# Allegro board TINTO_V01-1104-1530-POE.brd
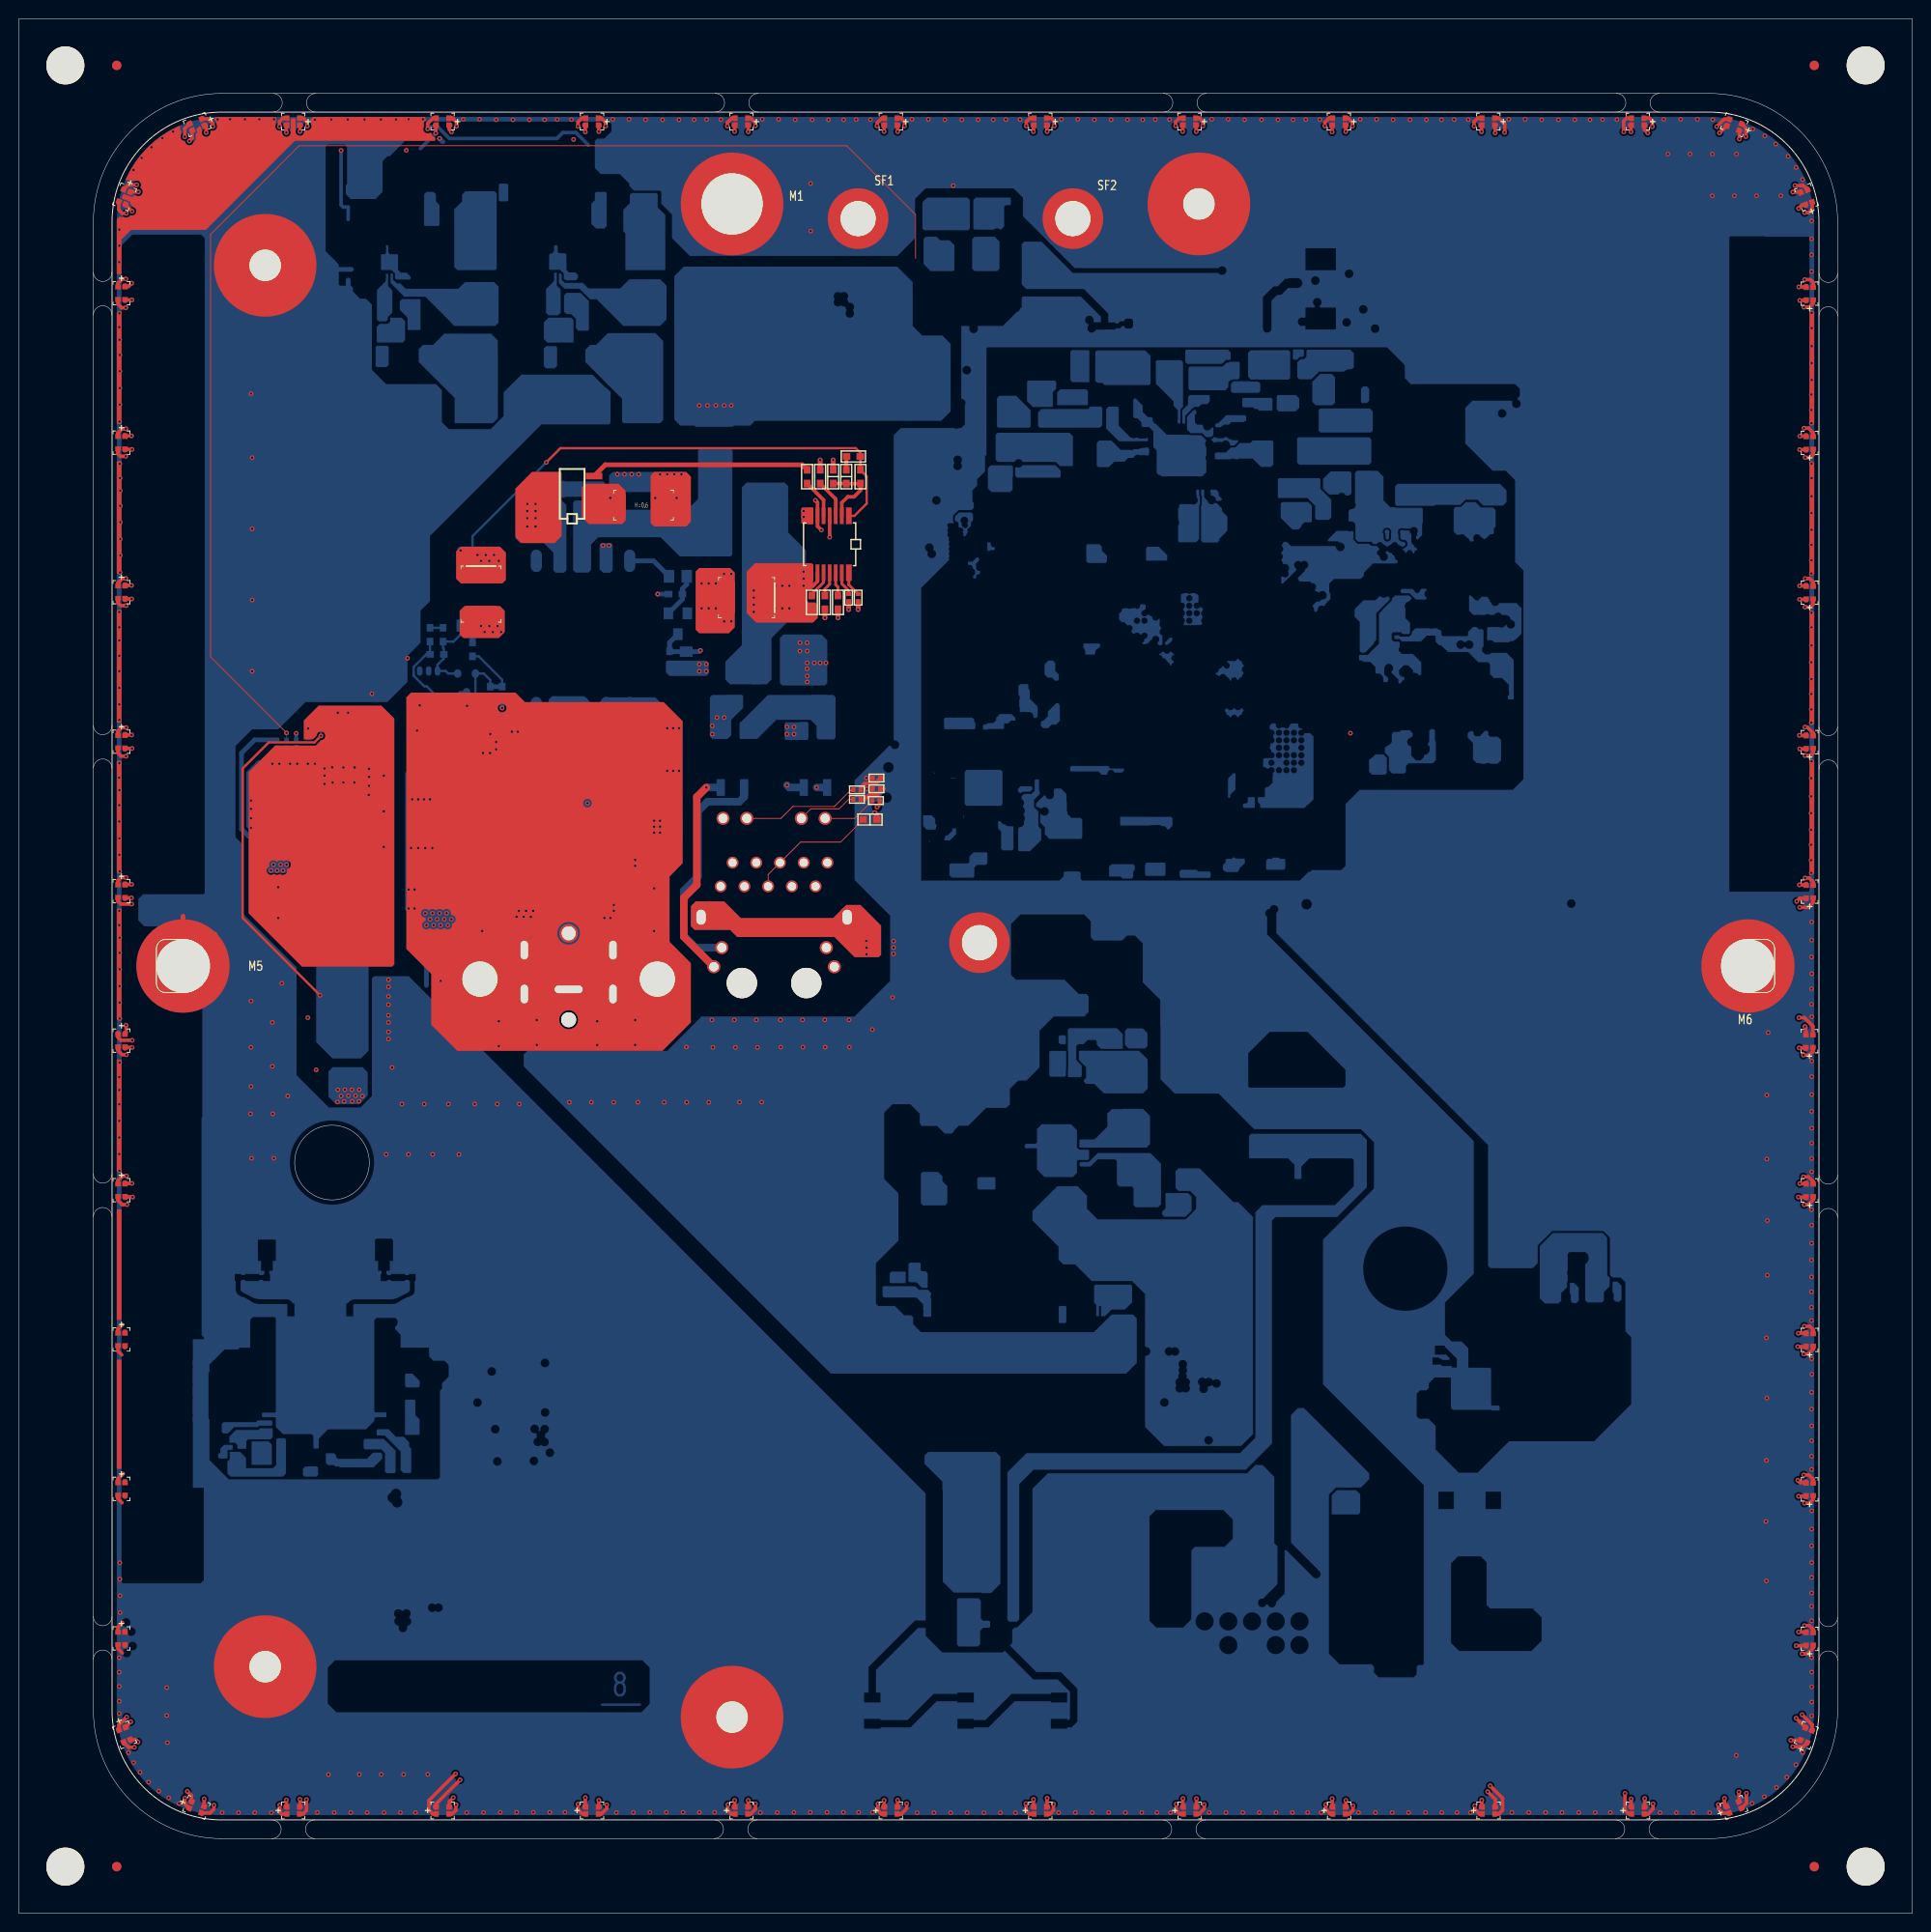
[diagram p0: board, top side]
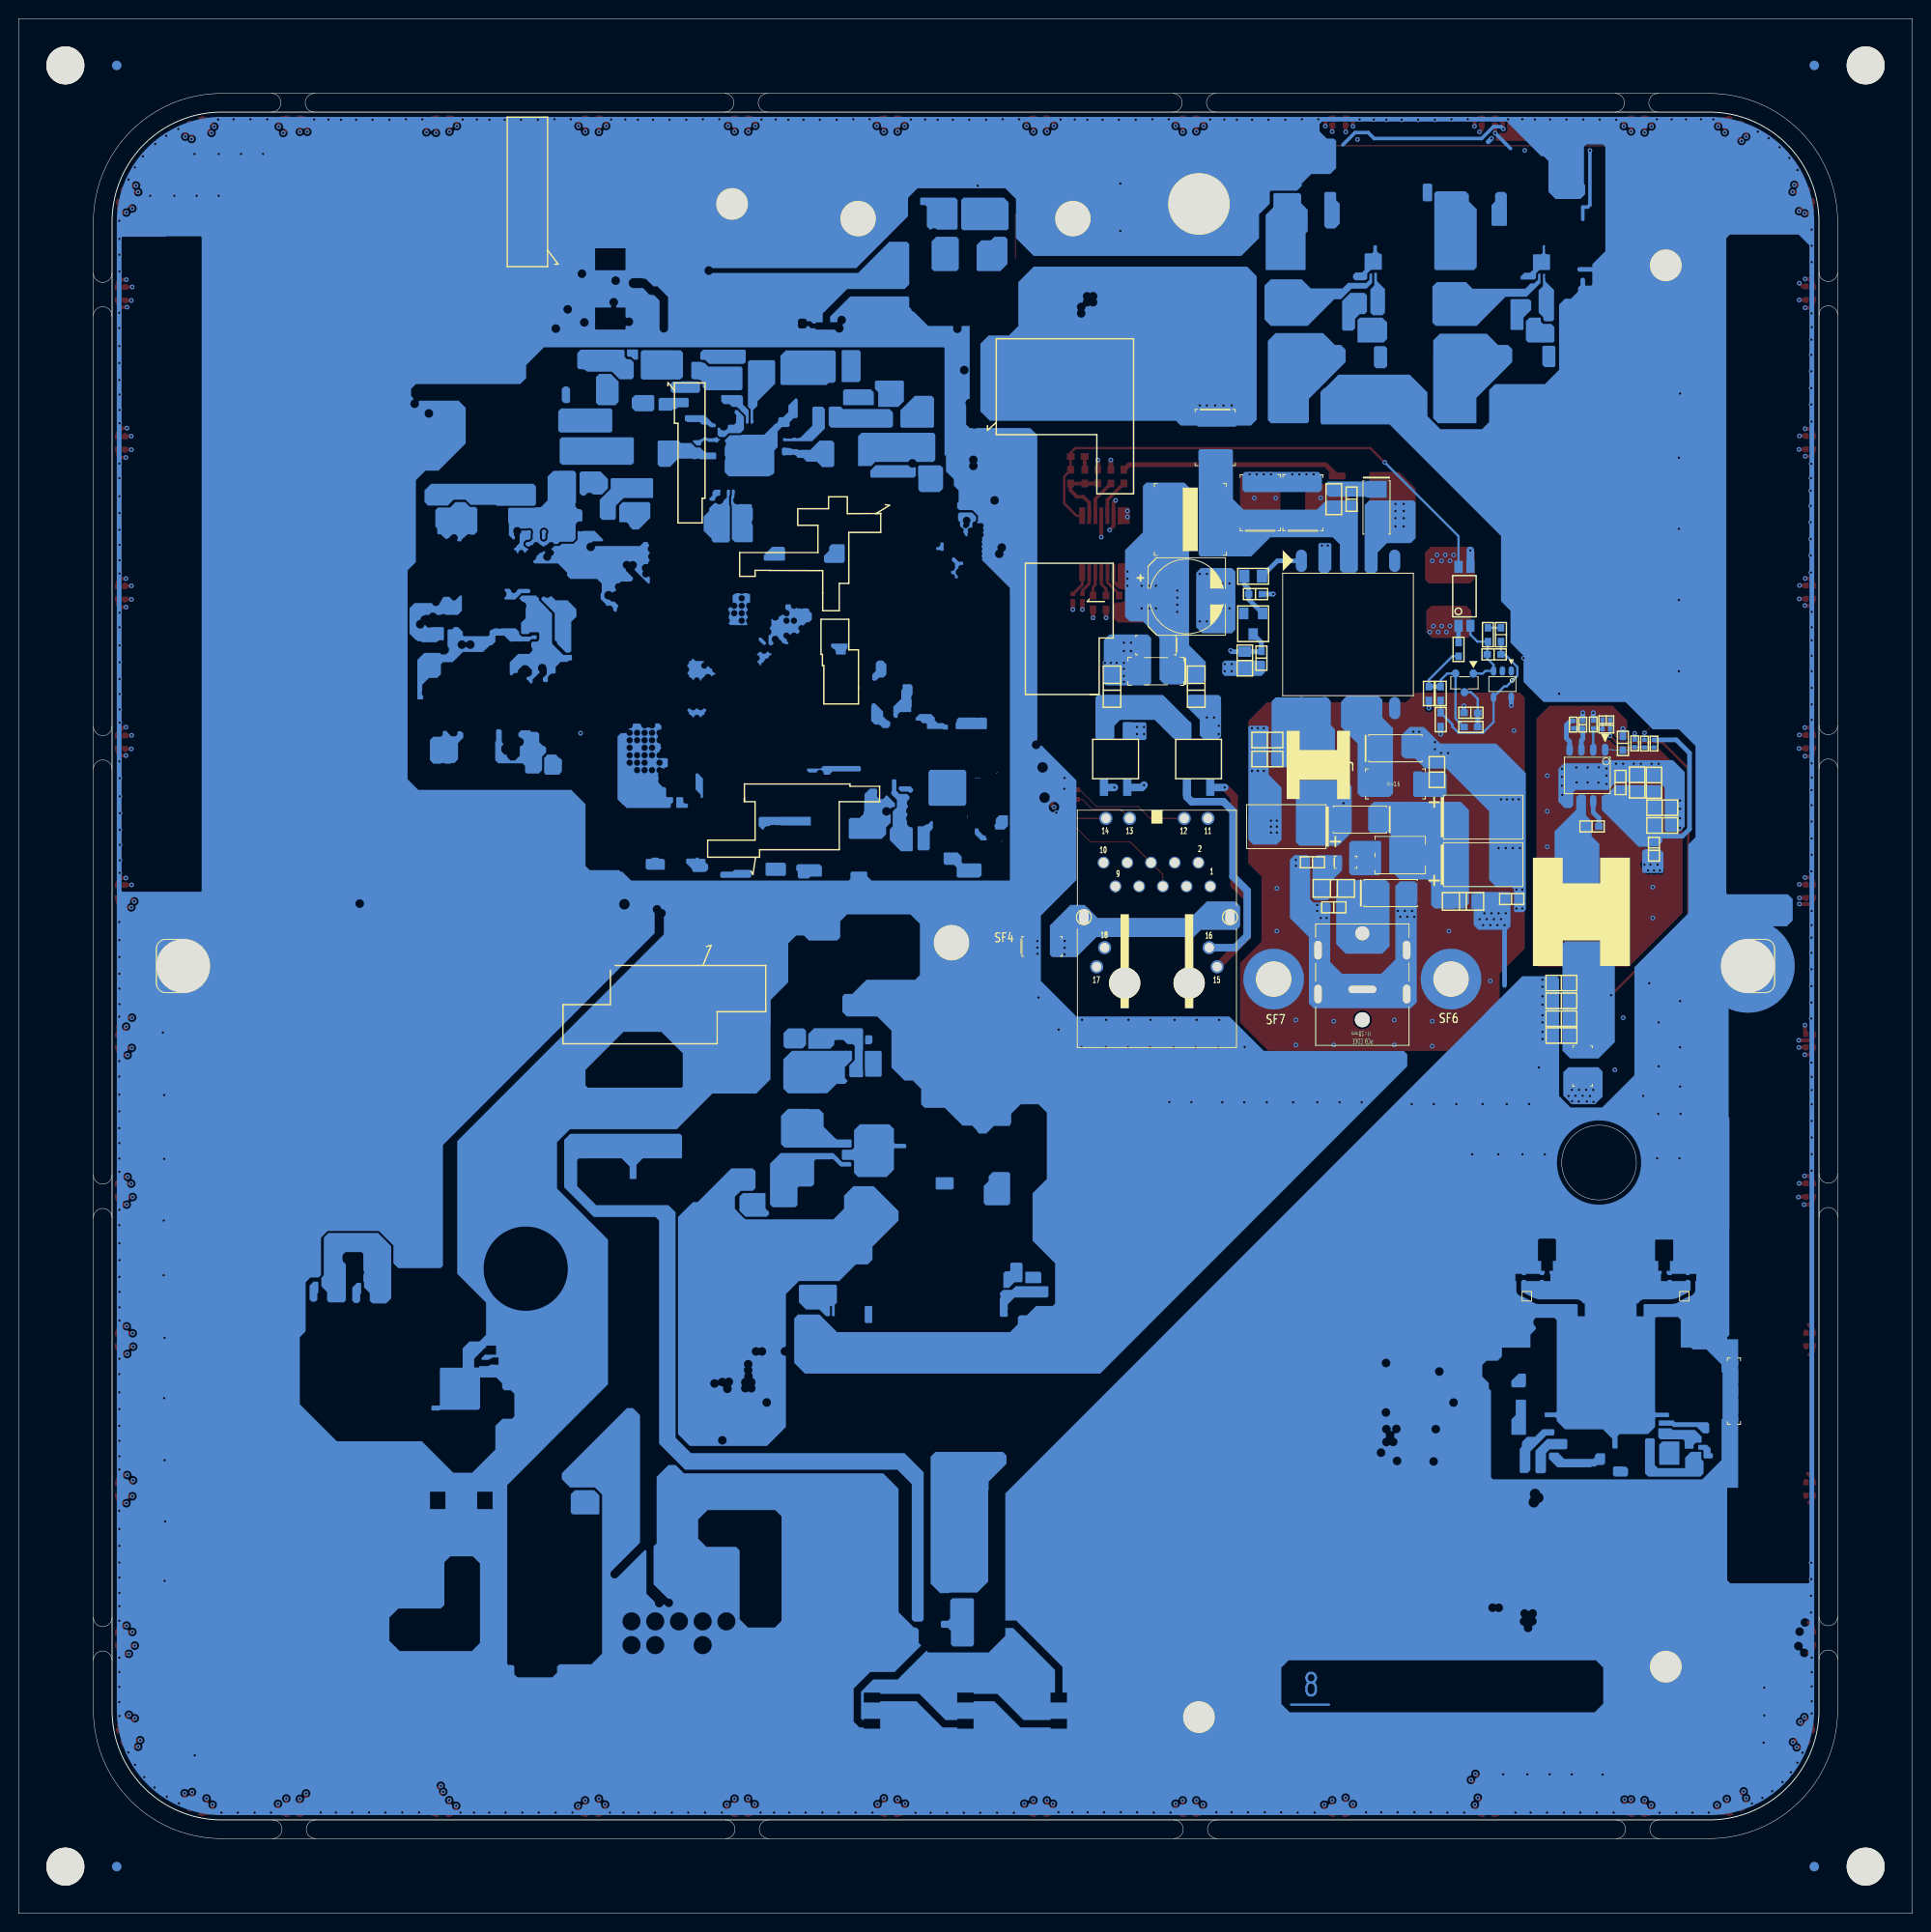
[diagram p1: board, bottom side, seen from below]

Outline 202.8 x 202.8 mm; copper layers: TOP, GND1, IN1, VCC1, VCC2, IN2, GND2, BOTTOM. Coordinates in mm from the lower left corner of the outline.
Outline path: circle c33.55,80.36 r4 ; 8,171.07 arc(9,172.07) 10,171.07 ; 8,122.56 arc(9,123.56) 10,122.56 ; 8,74.55 arc(9,75.55) 10,74.55 ; 8,27.18 arc(9,28.18) 10,27.18 ; 10,175.67 arc(9,174.67) 8,175.67 ; 10,127.16 arc(9,126.16) 8,127.16 ; 10,79.15 arc(9,78.15) 8,79.15 ; 10,31.78 arc(9,30.78) 8,31.78 ; 27.11,10 arc(28.11,9) 27.11,8 ; 27.23,194.8 arc(28.23,193.8) 27.23,192.8 ; 31.71,8 arc(30.71,9) 31.71,10 ; 31.83,192.8 arc(30.83,193.8) 31.83,194.8 ; 74.48,10 arc(75.48,9) 74.48,8 ; 74.6,194.8 arc(75.6,193.8) 74.6,192.8 ; 79.08,8 arc(78.08,9) 79.08,10 ; 79.2,192.8 arc(78.2,193.8) 79.2,194.8 ; 122.49,10 arc(123.49,9) 122.49,8 ; 122.6,194.8 arc(123.6,193.8) 122.6,192.8 ; 127.09,8 arc(126.09,9) 127.09,10 ; 127.2,192.8 arc(126.2,193.8) 127.2,194.8 ; 171,10 arc(172,9) 171,8 ; 171.12,194.8 arc(172.12,193.8) 171.12,192.8 ; 175.6,8 arc(174.6,9) 175.6,10 ; 175.72,192.8 arc(174.72,193.8) 175.72,194.8 ; 192.8,170.97 arc(193.8,171.97) 194.8,170.97 ; 192.8,122.46 arc(193.8,123.46) 194.8,122.46 ; 192.8,74.45 arc(193.8,75.45) 194.8,74.45 ; 192.8,27.08 arc(193.8,28.08) 194.8,27.08 ; 194.8,175.57 arc(193.8,174.57) 192.8,175.57 ; 194.8,127.06 arc(193.8,126.06) 192.8,127.06 ; 194.8,79.05 arc(193.8,78.05) 192.8,79.05 ; 194.8,31.68 arc(193.8,30.68) 192.8,31.68 ; 0,202.8 0,0 202.8,0 202.8,202.8 0,202.8 ; 8,181.06 arc(12.03,190.77) 21.74,194.8 181.06,194.8 arc(190.77,190.77) 194.8,181.06 194.8,21.74 arc(190.77,12.03) 181.06,8 21.74,8 arc(12.03,12.03) 8,21.74 8,181.06 ; 14.75,103.25 arc(15.04,103.96) 15.75,104.25 17.6,104.25 arc(20.45,101.4) 17.6,98.55 15.75,98.55 arc(15.04,98.84) 14.75,99.55 14.75,103.25 ; 185.2,104.25 187.05,104.25 arc(187.76,103.96) 188.05,103.25 188.05,99.55 arc(187.76,98.84) 187.05,98.55 185.2,98.55 arc(182.35,101.4) 185.2,104.25

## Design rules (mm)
constraint set DEFAULT: min track width 0.102
net group 50OHM-4(4.5): nets EMMC_CLK EMMC_CMD
net group GTX_CLK: nets GTX_CLK RGMII_TXCLK
net group LCD_CLK_N: nets LCD_CLK_N LVDS1_CLK_P
net group LCD_CLK_P: nets LCD_CLK_P LVDS1_CLK_N
net group LCD_TX0_N: nets LCD_TX0_N LVDS1_TX0_P
net group LCD_TX0_P: nets LCD_TX0_P LVDS1_TX0_N
net group LCD_TX1_N: nets LCD_TX1_N LVDS1_TX1_P
net group LCD_TX1_P: nets LCD_TX1_P LVDS1_TX1_N
net group LCD_TX2_N: nets LCD_TX2_N LVDS1_TX2_P
net group LCD_TX2_P: nets LCD_TX2_P LVDS1_TX2_N
net group LCD_TX3_N: nets LCD_TX3_N LVDS1_TX3_P
net group LCD_TX3_P: nets LCD_TX3_P LVDS1_TX3_N
net group PHY_RST: nets PHY_RST RGMII_NRST
net group PHY_RX_CLK: nets PHY_RX_CLK RGMII_RXCLK
net group PWR-8: nets VDDHIGH_IN VDDHIGH_VPH
net group PWR-16: nets GEN_1V8 VGEN4_1V8
net group SD3_CLK: nets SD3_CLK SD_CLK_CN
net group SD3_CMD: nets SD3_CMD SD_CMD_CN
net group SD3_DATA0: nets SD3_DATA0 SD_DAT0_CN
net group SD3_DATA1: nets SD3_DATA1 SD_DAT1_CN
net group SD3_DATA2: nets SD3_DATA2 SD_DAT2_CN
net group SD3_DATA3: nets SD3_DATA3 SD_DAT3_CN
net group SD4_DA0: nets SD4_DA0 SD4_DATA0
net group SD4_DA1: nets SD4_DA1 SD4_DATA1
net group SD4_DA2: nets SD4_DA2 SD4_DATA2
net group SD4_DA3: nets SD4_DA3 SD4_DATA3
net group SD4_DA4: nets SD4_DA4 SD4_DATA4
net group SD4_DA5: nets SD4_DA5 SD4_DATA5
net group SD4_DA6: nets SD4_DA6 SD4_DATA6
net group SD4_DA7: nets SD4_DA7 SD4_DATA7
net group AUD3: nets AUD3_RXD AUD3_TXC AUD3_TXD AUD3_TXFS
net group CLK-20: nets CLK1_N CLK1_P CLK1_P_N CLK1_P_R
net group DDR_CLK: nets DRAM_SDCLK0 DRAM_SDCLK0_B DRAM_SDCLK1_B
net group DDR_CMD: nets DRAM_A0 DRAM_A1 DRAM_A2 DRAM_A3 DRAM_A4 DRAM_A5 DRAM_A6 DRAM_A7 DRAM_A8 DRAM_A9 DRAM_A10 DRAM_A11 DRAM_A12 DRAM_A13 DRAM_A14 DRAM_A15 DRAM_CAS_B DRAM_RAS_B DRAM_SDBA0 DRAM_SDBA1 DRAM_SDBA2 DRAM_WE_B
net group DDR_CTL: nets DRAM_CS0_B DRAM_CS1_B DRAM_SDCKE0 DRAM_SDCKE1 DRAM_SDODT0 DRAM_SDODT1
net group DDR_DATA0: nets DRAM_D0 DRAM_D4 DRAM_D7 DRAM_DQM0
net group DDR_DATA1: nets DRAM_D8 DRAM_D9 DRAM_D10 DRAM_D13 DRAM_DQM1
net group DDR_DATA2: nets DRAM_D16 DRAM_D17 DRAM_D20 DRAM_DQM2
net group DDR_DATA3: nets DRAM_D24 DRAM_D29 DRAM_DQM3
net group DDR_DQS: nets DRAM_SDQS0 DRAM_SDQS0_B DRAM_SDQS1 DRAM_SDQS1_B DRAM_SDQS2 DRAM_SDQS2_B DRAM_SDQS3 DRAM_SDQS3_B
net group DDR_OT: nets DRAM_RESET_B
net group EMMC_CLK: nets SD4_CLK
net group EMMC_CMD: nets SD4_CMD
net group GND: nets GND
net group I2C: nets I2C1_SCL I2C1_SDA I2C2_SCL I2C2_SDA I2C3_SCL I2C3_SDA PMIC_SCL PMIC_SDA
net group LAN_GMII: nets RGMII_TRXN0 RGMII_TRXN1 RGMII_TRXN2 RGMII_TRXN3 RGMII_TRXP0 RGMII_TRXP1 RGMII_TRXP2 RGMII_TRXP3
net group LVDS_3W-S11.4(12): nets LVDS0_CLK_N LVDS0_CLK_P LVDS0_TX0_N LVDS0_TX0_P LVDS0_TX1_N LVDS0_TX1_P LVDS0_TX2_N LVDS0_TX2_P LVDS0_TX3_N LVDS0_TX3_P
net group PWR: nets 2V5_RGMII DDR_1V5_L DDR_VREF DVDDL_RGMII EMMC_VDD ETH_RBIAS ETH_VDDIO_REG GEN_3V3_IN GEN_3V3_PMIC LAN_AVDD33 LAN_AVDDL LAN_DVDD_SW LCD_AVDD LCD_BL+ LCD_BL- LCD_PWM LCD_SUP LCD_VCOM LCD_VCOM_IN LCD_VDD LCD_VGH LCD_VGL LVDS_2V5 N2030210 N17702392 N18409851 N19092772 N19097147 N24036489 N24124655 N24230966 N24230987 N24253285 NFC_PVDD NFC_SIMVCC NFC_SVDD NFC_VBAT NVCC_CSI NVCC_EIM NVCC_MIPI NVCC_RGMII NVCC_SD1 NVCC_SD2 PCIE_VP PMIC_VCORE PMIC_VCOREREF PMIC_VDDOTP PMIC_VSNVS RTC_3V SATA_VP SENSOR_3V3 SENSOR_5V SET_1V8 SET_3V3 SW1CLX SYS_3V SYS_5V USB_H1_VBUS USB_OTG_VBUS VCCRTC VCOREDIG VDD5V_IN VDD_SNVS_CAP VDDCORE_R VDDSOC_R VGEN1_1V5 VGEN6_3V3 VOUT_1V8 VOUT_3V3 WLAN_3VIN
net group PWR-10: nets RF_ANT1 RF_ANT1_CN RF_ANT2 RF_ANT2_CN
net group PWR-12: nets NFC_1.8VDDM NFC_3VDDM NVCC_PLL_LDO NVCC_PLL_OUT
net group PWR-20: nets ETH_3V3 GEN_3V3 HDMI_VP N22820015 N24165639 N27686456 N27686764 NVCC_3V3 OTG_VBUS PA_3V3 VDD12V_POE VDD_IO VGEN2_1V5
net group PWR-32: nets POE_RTN
net group PWR-40: nets AUX_3V15
net group PWR-80: nets VDDPU VDDSOC VDDSOC_CAP
net group PWR-100: nets DDR_1V5 VDD13_12 VDD_ARM_CAP VDDCORE
net group PWR-240: nets PMU3V
net group PWR-W6: nets GEN_2V5 HDMI_VPH PCIE_VPH SATA_VPH VGEN5_2V8 VSNVS_3V0
net group PWR-W32: nets PMIC_5V POE_VDD POE_VDD_CN POE_VSS POE_VSS_CN VDD_PSE_M1 VDD_PSE_M2 VDD_PSE_P1 VDD_PSE_P2
net group PWR_GATE: nets 3V_SW 5V_SW GEN_3V3_SW N17701522 N18409953 N39184104 N39184195 N39184527 N39184670 SW1LX SW3LX SW4LX SW_T
net group RGMII: nets RGMII_MDC RGMII_MDIO RGMII_RXD0 RGMII_RXD1 RGMII_RXD2 RGMII_RXD3 RGMII_RXDV RGMII_TXD0 RGMII_TXD1 RGMII_TXD2 RGMII_TXD3 RGMII_TXEN
net group S-10: nets G_LED_FB1 G_LED_FB2 G_LED_FB3 G_LED_FB4 G_LED_FB5 G_LED_FB6 LED_G_POWER LED_GREEN LED_R_POWER LED_RED LED_YELLOW N17701582 N17701584 N17701586 N17701588 N17701590 N17701592 N17701594 N17701596 N17701598 N17701600 N17701602 N17701604 N17701700 N17701702 N17701704 N17701706 N17702195 N17702197 N17702222 N17702224 N17702236 N17702240 N17702242 N17702244 N17702269 N17702271 N17702317 N17702327 N17702414 N17702416 N17702418 N17702420 N17702422 N17702424 N17702426 N17702428 N17702430 N17702432 N17702434 N17702436 N17702438 N17702440 N17702495 N17702497 N17702499 N17702501 N17702503 N17702505 N17702507 N17702509 N17702511 N17702513 N17702515 N17702517 N17702581 N17702583 N17736265 N17736966 N17737669 N17738374 N17739081 N17739790 N17740501 N17741214 N17741929 N17742646 N17743365 N17744086 N17744809 N17745534 N17756919 N17756921 N17756923 N17756925 N17756927 N17756929 N17756931 N17756933 N17756935 N17756937 N17756939 N17756941 N17756943 N17756945 R_LED_IFB1 R_LED_IFB2 R_LED_IFB3 R_LED_IFB4 R_LED_IFB5 R_LED_IFB6 RGMII_LED_10_100 RGMII_LED_1000 RGMII_LED_ACT
net group S-20: nets N25586908 N28364944 N28380123
net group S_2W-S8(9): nets UART5_CTS UART5_RTS UART5_RXD UART5_TXD
net group SD: nets SD2_CD_B SD2_DATA4 SD2_DATA5 SD2_DATA6 SD2_DATA7 SD2_WP SD3_CD_B SD3_DATA4 SD3_DATA5 SD3_DATA6 SD3_DATA7 SD3_WP SD_CD#_CN
net group UART: nets UART1_RX UART1_RX_CN UART1_TX UART1_TX_CN UART3_RXD UART3_TXD
net group UART5: nets BT_CTS BT_RTS BT_RXD BT_TXD
net group USB: nets USB_HOST_DN USB_HOST_DP USB_OTG_DN USB_OTG_DP
net group XTAL: nets N27686566 N27686641 N27686643 N27686649 PHY_XTLI PHY_XTLO RTC_XTALI RTC_XTALO XTAL24_IN XTAL24_OUT

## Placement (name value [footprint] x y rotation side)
C27  -  [C0603]  87.23 153.78 90 top
C28  -  [C0603]  88.63 153.78 90 top
C49  2200pF  [C1812]  49.51 141.21 270 top
C52  -  [C1812]  77.96 140.83 180 top
C153  0.1uF  [C0603]  91.17 117.08 180 top
C233  2200pF  [C1812]  74.66 157.97 270 bottom
C248  -  [C1812]  65.26 150.99 90 bottom
C249  -  [C1812]  69.83 150.99 90 bottom
C250  0.01uF  [C0603]  60.05 151.37 90 bottom
C258  -  [CE_W830H830]  77.71 140.95 270 bottom
C259  -  [C0603]  70.34 141.21 180 bottom
C264  6800pF  [C0603]  44.05 136.86 270 bottom
C273  -  [C1206]  81.01 135.75 270 bottom
C275  0.22uF  [C0603]  69.71 134.35 270 bottom
C276  10pF  [C0603]  44.79 134.76 180 bottom
C278  -  [C0805]  71.48 134.1 270 bottom
C283  -  [C0603]  47.28 128.51 0 bottom
C284  15pF  [C0402]  32.77 127.77 0 bottom
C285  1uF  [C0402]  35.29 127.24 90 bottom
C286  0.1uF  [C0603]  31 125.23 270 bottom
C288  -  [C0805]  69.07 125.59 0 bottom
C291  -  [C0805]  69.07 123.55 0 bottom
C292  2200pF  [C0805]  50.91 122.16 90 bottom
C298  -  [C0805]  29.47 121.04 90 bottom
C299  -  [C0805]  27.67 121.01 90 bottom
C300  0.1uF  [C0603]  31.25 121.04 90 bottom
C305  -  [C0805]  26.78 118.35 180 bottom
C309  -  [C7343]  45.96 117.33 180 bottom
C310  -  [C0805]  26.78 116.44 180 bottom
C311  0.1uF  [C0603]  34.3 116.34 0 bottom
C313  -  [C7343]  67.04 116.32 0 bottom
C318  0.1uF  [C0603]  64.25 112.51 0 bottom
C320  -  [C7343]  45.96 112.25 180 bottom
C322  0.1uF  [C0603]  61.96 107.68 0 bottom
C323  0.1uF  [C0603]  42.91 108.57 180 bottom
C325  1000pF  [C1206]  93.2 103.49 90 bottom
C327  -  [C0805]  37.58 99.58 0 bottom
C328  -  [C0805]  37.58 97.67 0 bottom
C329  -  [C0805]  37.58 95.77 0 bottom
C331  -  [C0805]  37.58 93.96 0 bottom
CLIP15  -  [CLIP_92-1370]  19.1 55.89 90 bottom
CN3  -  [RJ45_18P_2PAD_JFM3811Q-FLP1-4F]  80.9 99.57 180 bottom
CN5  -  [DCJACK_2DC-G213-B28]  58.9 98.9 0 bottom
D9  -  [DIODE_SMA]  57.39 150.48 270 bottom
D10  -  [SOT23_123]  70.6 138.03 270 bottom
D11  -  [DIODE_SMA-L]  81.01 132.95 0 bottom
D12  BAV99  [SOT_23-NPNP]  47.97 131.71 270 bottom
D13  -  [DIODE_SMA]  55.36 124.7 180 bottom
D14  -  [DIODE_MDI-H2_7]  76.44 123.55 90 bottom
D15  -  [DIODE_MDI-H2_7]  85.33 123.55 90 bottom
D16  -  [DIODE_SMA]  59.17 117.08 0 bottom
D17  -  [DIODE_POWERDI_3]  54.85 113.27 270 bottom
D18  -  [DIODE_SMA]  55.86 109.2 180 bottom
FB9  UPB321611T-121Y-N  [L1206]  76.69 131.3 90 bottom
FB10  UPB321611T-121Y-N  [L1206]  85.71 131.3 90 bottom
FB12  PBY160808T-121Y-N  [L0603]  27.67 113.9 90 bottom
FB13  UPB321611T-121Y-N  [L1206]  61.96 109.71 0 bottom
FB14  UPB321611T-121Y-N  [L1206]  48.12 108.31 180 bottom
FS1  -  [PPTC0603]  60.69 112.51 90 bottom
L10  -  [L_CHOKE_670X670_CDRH6D28]  77.33 149.21 270 bottom
L12  -  [L_CHOKE_650X730-R185_350]  63.61 122.92 270 bottom
L14  -  [L_CHOKE_1040X1160]  35.44 107.2 270 bottom
LED1  -  [LEDX2_160X130X40_4P-1342]  29.4 191.78 0 top
LED2  -  [LEDX2_160X130X40_4P-1342]  45.4 191.78 0 top
LED3  -  [LEDX2_160X130X40_4P-1342]  61.4 191.78 0 top
LED4  -  [LEDX2_160X130X40_4P-1342]  77.4 191.78 0 top
LED5  -  [LEDX2_160X130X40_4P-1342]  93.41 191.78 0 top
LED6  -  [LEDX2_160X130X40_4P-1342]  109.41 191.78 0 top
LED7  -  [LEDX2_160X130X40_4P-1342]  125.39 191.78 0 top
LED8  -  [LEDX2_160X130X40_4P-1342]  141.39 191.78 0 top
LED9  -  [LEDX2_160X130X40_4P-1342]  157.39 191.78 0 top
LED10  -  [LEDX2_160X130X40_4P-1342]  173.39 191.78 0 top
LED11  -  [LEDX2_160X130X40_4P-1342]  19.11 191.46 21.6 top
LED12  -  [LEDX2_160X130X40_4P-1342]  183.73 191.44 339.3 top
LED13  -  [LEDX2_160X130X40_4P-1342]  11.34 183.73 68.5 top
LED14  -  [LEDX2_160X130X40_4P-1342]  191.47 183.69 290.8 top
LED15  -  [LEDX2_160X130X40_4P-1342]  11.01 173.42 90 top
LED16  -  [LEDX2_160X130X40_4P-1342]  191.81 173.37 270 top
LED17  -  [LEDX2_160X130X40_4P-1342]  11.01 157.42 90 top
LED18  -  [LEDX2_160X130X40_4P-1342]  191.81 157.39 270 top
LED19  -  [LEDX2_160X130X40_4P-1342]  11.01 141.41 90 top
LED20  -  [LEDX2_160X130X40_4P-1342]  191.81 141.36 270 top
LED21  -  [LEDX2_160X130X40_4P-1342]  11.01 125.41 90 top
LED22  -  [LEDX2_160X130X40_4P-1342]  191.81 125.36 270 top
LED23  -  [LEDX2_160X130X40_4P-1342]  11.01 109.41 90 top
LED24  -  [LEDX2_160X130X40_4P-1342]  191.81 109.36 270 top
LED25  -  [LEDX2_160X130X40_4P-1342]  11.01 93.41 90 top
LED26  -  [LEDX2_160X130X40_4P-1342]  191.78 93.35 270 top
LED27  -  [LEDX2_160X130X40_4P-1342]  11.01 77.41 90 top
LED28  -  [LEDX2_160X130X40_4P-1342]  191.81 77.38 270 top
LED29  -  [LEDX2_160X130X40_4P-1342]  11.01 61.43 90 top
LED30  -  [LEDX2_160X130X40_4P-1342]  191.81 61.38 270 top
LED31  -  [LEDX2_160X130X40_4P-1342]  11.01 45.43 90 top
LED32  -  [LEDX2_160X130X40_4P-1342]  191.81 45.38 270 top
LED33  -  [LEDX2_160X130X40_4P-1342]  11.01 29.43 90 top
LED34  -  [LEDX2_160X130X40_4P-1342]  191.81 29.37 270 top
LED35  -  [LEDX2_160X130X40_4P-1342]  11.34 19.11 111.7 top
LED36  -  [LEDX2_160X130X40_4P-1342]  191.45 19.06 248.2 top
LED37  -  [LEDX2_160X130X40_4P-1342]  19.05 11.35 159 top
LED38  -  [LEDX2_160X130X40_4P-1342]  183.7 11.34 201.9 top
LED39  -  [LEDX2_160X130X40_4P-1342]  29.4 11.01 180 top
LED40  -  [LEDX2_160X130X40_4P-1342]  45.4 11.01 180 top
LED41  -  [LEDX2_160X130X40_4P-1342]  61.4 11.01 180 top
LED42  -  [LEDX2_160X130X40_4P-1342]  77.4 11.01 180 top
LED43  -  [LEDX2_160X130X40_4P-1342]  93.41 11.01 180 top
LED44  -  [LEDX2_160X130X40_4P-1342]  109.41 11.01 180 top
LED45  -  [LEDX2_160X130X40_4P-1342]  125.41 11.01 180 top
LED46  -  [LEDX2_160X130X40_4P-1342]  141.41 11.01 180 top
LED47  -  [LEDX2_160X130X40_4P-1342]  157.41 11.01 180 top
LED48  -  [LEDX2_160X130X40_4P-1342]  173.42 11.01 180 top
M1  -  [CTB1100Z700H650]  76.4 182.97 0 top
M2  -  [CTB1100Z380H330]  126.4 182.97 0 top
M3  -  [CTB1100Z380H330]  26.4 176.4 0 top
M5  -  [CTB1000Z620H570]  17.6 101.4 0 top
M6  -  [CTB1000Z620H570]  185.2 101.4 0 top
M7  -  [CTB1100Z380H330]  26.4 26.4 0 top
M10  -  [CTB1100Z380H330]  76.4 21 0 top
NOREF  -  [unnamed]  5 5 0 top
NOREF#2  -  [unnamed]  197.8 197.8 0 top
NOREF#3  -  [unnamed#2]  10.5 197.8 0 top
NOREF#4  -  [unnamed]  197.8 5 0 top
NOREF#5  -  [unnamed#2]  192.3 197.8 0 top
NOREF#6  -  [#3]  26.4 26.4 0 top
NOREF#7  -  [unnamed]  5 197.8 0 top
NOREF#8  -  [unnamed#2]  10.5 5 0 top
NOREF#9  -  [unnamed#2]  192.3 5 0 top
NOREF#10  -  [unnamed#2]  10.5 197.8 180 bottom
NOREF#11  -  [unnamed#2]  10.5 5 180 bottom
NOREF#12  -  [unnamed#2]  192.3 197.8 180 bottom
NOREF#13  -  [unnamed#2]  192.3 5 180 bottom
Q1  Si4848DY-T1  [SMD8A-184]  59.27 151.94 90 top
R10  -  [R0603]  89.39 155.94 0 top
R11  -  [R0603]  85.84 153.78 270 top
R16  -  [R0603]  84.44 153.78 90 top
R17  3K  [R0603]  90.15 153.78 90 top
R20  0.39  [R2010]  66.91 150.73 0 top
R48  -  [R0402]  88.88 140.83 270 top
R49  210K  [R0402]  89.9 140.83 270 top
R54  -  [R0603]  84.95 140.32 90 top
R55  -  [R0603]  86.34 140.32 90 top
R56  -  [R0603]  87.74 140.32 90 top
R93  10K  [R0402]  91.86 121.52 0 top
R96  10K  [R0402]  91.86 120.37 0 top
R97  220  [R0402]  89.77 120.25 0 top
R98  220  [R0402]  89.77 119.24 0 top
R99  0  [R0402]  91.8 119.11 0 top
R172  160K  [R0805]  61.96 151.37 90 bottom
R193  49.9  [R0805]  70.6 143.11 180 bottom
R208  143K  [R0603]  45.45 136.86 90 bottom
R213  4.02K  [R0603]  48.6 135.29 90 bottom
R216  -  [R0603]  50.51 130.56 270 bottom
R217  -  [R0603]  51.78 130.56 90 bottom
R219  -  [R0603]  50.51 127.77 270 bottom
R223  124K  [R0402]  32.77 126.75 0 bottom
R234  22.1K  [R0402]  34.17 127.26 90 bottom
R235  100K  [R0402]  36.3 127.24 90 bottom
R236  -  [R0603]  47.28 126.98 180 bottom
R237  2.2K  [R0402]  29.73 125.23 270 bottom
R238  10K  [R0402]  27.67 125.21 270 bottom
R239  0  [R0402]  28.69 125.21 270 bottom
R243  10  [R2010]  55.36 120.89 180 bottom
R301  -  [R1206]  35.31 90.69 270 bottom
SF1  -  [NUT_CT650BZ410H370]  89.9 181.4 0 top
SF2  -  [NUT_CT650BZ410H370]  112.9 181.4 0 top
SF4  -  [NUT_CT650BZ410H370]  102.9 103.9 180 bottom
SF6  -  [NUT_CT650BZ410H370]  49.4 100 180 bottom
SF7  -  [NUT_CT650BZ410H370]  68.4 100 180 bottom
T1  -  [TRANSFOMER_10_W1400L1765P250]  60.44 136.89 0 bottom
U4  TPS23753PWR  [TSSOP14__65M_240-H1_2]  86.85 146.54 180 top
U22  TCMT1107  [SOP4_1_27M]  47.97 140.98 180 bottom
U25  TL431ACDBVR  [SOT_23_5-H1_45]  43.9 131.58 270 bottom
U27  -  [SOIC_8_PWR]  34.81 121.8 270 bottom

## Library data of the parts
C27 C283 = 10-52868-00
C28 = 10-51475-00
C49 C233 = 10-51542-00
C52 C248 C249 = 10-51641-00
C153 C300 C311 C318 C322 C323 = 10-52979-00
C250 = 10-51254-02
C258 = 10-30880-01
C259 = 10-51643-00
C264 = 10-51177-00
C273 = 10-51546-00
C275 = 10-52872-00
C276 = 10-51452-00
C278 = 10-51639-00
C284 = 10-52833-00
C285 = 10-52935-09
C286 = NU_10-52979-00
C288 C291 C298 C299 C305 C310 C327-C329 C331 = 10-51616-00
C292 = 10-51540-00
C309 C313 C320 = 10-40806-01
C325 = 10-51179-00
CLIP15 = 24-89PDQ-01
CN3 = 20-26646-01
CN5 = 20-26641-01
D9 = 06-10840-02
D10 = 06-10588-02
D11 = 06-10836-01
D12 = 06-10571-05
D13 D16 = 06-10873-01
D14 D15 = 06-10963-01
D17 = 06-10944-01
D18 = 06-10961-01
FB9 FB10 FB13 FB14 = 21-92453-01
FB12 = 21-92386-03
FS1 = 21-10724-02
L10 = 12-00911-01
L12 = 12-01952-02
L14 = 12-02494-01
LED1-LED48 = 21-92779-01
M1 = CTB1100Z700H650
M2 M3 M7 M10 = CTB1100Z380H330
M5 M6 = CTB1000Z620H570
Q1 = 06-24124-01
R10 R11 R217 = 11-14214-00
R16 = 11-14295-00
R17 = 11-14344-00
R20 = 11-13374-00
R48 = 11-14874-00
R49 = 11-13385-00
R54 = 11-14539-00
R55 = 11-13322-00
R56 R236 = 11-14280-00
R93 R96 = 11-14297-00
R97 R98 = 11-14651-00
R99 = 11-14294-00
R172 = 11-13371-00
R193 = 11-13372-00
R208 = 11-12689-00
R213 = 11-13030-00
R216 = 11-13568-00
R219 = 11-13338-00
R223 = 11-13147-00
R234 = 11-14561-00
R235 = 11-12834-00
R237 = 11-14560-00
R238 = NU_11-14297-00
R239 = NU_11-14294-00
R243 = 11-13373-00
R301 = 11-14210-00
SF1 SF2 = 24-12459-00
SF4 SF6 SF7 = 24-12460-00
T1 = 12-02504-01
U4 = 05-32472-01
U22 = 05-32471-01
U25 = 05-32473-01
U27 = 05-32927-01

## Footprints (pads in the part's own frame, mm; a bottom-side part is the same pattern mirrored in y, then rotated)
C0402
  rect 0.457x0.508 smd: 1(-0.4,0) 2(0.4,0)
C0603
  rect 0.813x0.711 smd: 1(-0.737,0) 2(0.737,0)
C0805
  rect 1.118x1.372 smd: 1(-0.95,0) 2(0.95,0)
C1206
  custom 0.25x0.25 smd: 1(0,1.45) 2(0,-1.45)
C1812
  custom 0.35x0.35 smd: 1(-1.95,0) 2(1.95,0)
C7343
  custom 0.475x0.475 smd: 1(-3.1,0) 2(3.1,0)
CE_W830H830
  oval 1.4x3.6 smd: 1(0,-3.4) 2(0,3.4)
CLIP_92-1370
  rect 1.1x0.9 smd: 1(0,0)
  rect 0.6x0.9 smd: 2(3,0) 3(-3,0)
  rect 1.5x0.9 smd: 4(-1.65,0) 5(1.65,0)
CTB1000Z620H570
  round 10 hole 5.7: 1(0,0)
CTB1100Z380H330
  round 11 hole 3.3: 1(0,0)
CTB1100Z700H650
  round 11 hole 6.5: 1(0,0)
DCJACK_2DC-G213-B28
  round 1.6 hole 1.6 unplated: (0,3.25)
  round 2 hole 1.5: 1(0,-6)
  oval 3.6x1.4 hole 3x0.8: 2(0,0)
  oval 1.4x2.6 hole 0.8x2: PAD1(-4.75,0.5) PAD2(4.75,0.5) PAD3(-4.75,-4.2) PAD4(4.75,-4.2)
DIODE_MDI-H2_7
  rect 1.803x0.889 smd: 1(3.048,-1.25) 2(3.048,1.25) 3(-3.048,1.25) 4(-3.048,-1.25)
DIODE_POWERDI_3
  custom 0.275x0.275 smd: A1(-0.92,-2.9) A2(0.92,-2.9)
  custom 1x1 smd: C(0,1.05)
DIODE_SMA
  rect 1.8x2.2 smd: A(1.95,0) C(-1.95,0)
DIODE_SMA-L
  custom 0.45x0.45 smd: A(2,0) C(-2,0)
L0603
  rect 0.813x0.711 smd: 1(-0.737,0) 2(0.737,0)
L1206
  rect 1.168x1.575 smd: 1(-1.473,0) 2(1.473,0)
L_CHOKE_650X730-R185_350
  rect 1.85x3.5 smd: 1(-2.775,0) 2(2.775,0)
L_CHOKE_670X670_CDRH6D28
  rect 7.3x2.65 smd: 1(0,-2.325) 2(0,2.325)
L_CHOKE_1040X1160
  custom 0.75x0.75 smd: 1(-4.8,0) 2(4.8,0)
LEDX2_160X130X40_4P-1342
  custom 0.15x0.15 smd: 1(0.725,-0.375) 2(-0.725,-0.375) 3(0.725,0.375) 4(-0.725,0.375)
NUT_CT650BZ410H370
  round 6.5 hole 3.7: 1(0,0)
PPTC0603
  custom 0.15x0.15 smd: 1(0,0.7) 2(0,-0.7)
R0402
  rect 0.457x0.508 smd: 1(-0.4,0) 2(0.4,0)
R0603
  rect 0.813x0.711 smd: 1(-0.737,0) 2(0.737,0)
R0805
  rect 1.118x1.372 smd: 1(-0.95,0) 2(0.95,0)
R1206
  custom 0.225x0.225 smd: 1(-1.5,0) 2(1.5,0)
R2010
  custom 0.25x0.25 smd: 1(-2.4,0) 2(2.4,0)
RJ45_18P_2PAD_JFM3811Q-FLP1-4F
  round 3.25 hole 3.25 unplated: (-3.45,0) (3.45,0)
  round 1.27 hole 0.9: 1(5.715,10.35) 2(4.445,12.89) 3(3.175,10.35) 4(1.905,12.89) 5(0.635,10.35) 6(-0.635,12.89) 7(-1.905,10.35) 8(-3.175,12.89) 9(-4.445,10.35) 10(-5.715,12.89)
  round 1.4 hole 1: 11(5.465,17.63) 12(2.925,17.63) 13(-2.925,17.63) 14(-5.465,17.63) 15(6.45,1.74) 16(5.6,3.79) 17(-6.45,1.74) 18(-5.6,3.79)
  oval 1.6x2.2 hole 1x1.6: PAD1(-7.825,7.05) PAD2(7.825,7.05)
SMD8A-184
  rect 0.711x1.778 smd: 1(-1.905,-2.34) 2(-0.635,-2.34) 3(0.635,-2.34) 4(1.905,-2.34) 5(1.905,2.34) 6(0.635,2.34) 7(-0.635,2.34) 8(-1.905,2.34)
SOIC_8_PWR
  oval 1.3x0.7 smd: 1(-2.75,1.905) 2(-2.75,0.635) 3(-2.75,-0.635) 4(-2.75,-1.905) 5(2.75,-1.905) 6(2.75,-0.635) 7(2.75,0.635) 8(2.75,1.905)
  rect 2.3x3 smd: PAD1(0,0)
SOP4_1_27M
  rect 0.889x1.295 smd: 1(-0.635,-3.15) 2(0.635,-3.15) 3(0.635,3.15) 4(-0.635,3.15)
SOT23_123
  rect 1.27x1.016 smd: 1(-1.118,1.016) 2(-1.118,-1.016) 3(1.118,0)
SOT_23-NPNP
  oval 0.9x0.8 smd: N(-1,-0.95) NP(1,0) P(-1,0.95)
SOT_23_5-H1_45
  oval 1x0.6 smd: 1(-1.4,0.95) 2(-1.4,0) 3(-1.4,-0.95) 4(1.4,-0.95) 5(1.4,0.95)
TRANSFOMER_10_W1400L1765P250
  oval 1.2x2.4 smd: 1(5,-7.88) 2(2.5,-7.88) 3(0,-7.88) 4(-2.5,-7.88) 5(-5,-7.88) 6(-5,7.88) 7(-2.5,7.88) 8(0,7.88) 9(2.5,7.88) 10(5,7.88)
TSSOP14__65M_240-H1_2
  rect 0.61x1.778 smd: 1(-2.052,-3.048) 7(2.052,-3.048) 8(2.052,3.048) 14(-2.052,3.048)
  rect 0.406x1.778 smd: 2(-1.3,-3.048) 3(-0.65,-3.048) 4(0,-3.048) 5(0.65,-3.048) 6(1.3,-3.048) 9(1.3,3.048) 10(0.65,3.048) 11(0,3.048) 12(-0.65,3.048) 13(-1.3,3.048)
unnamed
  round 4.064 hole 4.064 unplated: (0,0)
unnamed#2
  round 1.016 smd: 1(0,0)

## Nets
5V_SW: C311.2(TP-2) L14.1 U27.6
5VDDM: R301.2(TP-2)
5VDDM_VIN: C298.1 C299.1 C300.1(TP-1) C305.1 C310.1 FB12.2 R238.1(TP-1) U27.8
GND: C49.2 C153.1(TP-1) C233.1 C283.2 C285.2(TP-2) C286.1(TP-1) C288.2 C291.2 C292.2(TP-2) C298.2 C299.2 C300.2(TP-2) C305.2 C309.2 C310.2 C313.2 C318.2(TP-2) C320.2 C322.2(TP-2) C323.2(TP-2) C325.1(TP-1) C327.2 C328.2 C329.2 C331.2 CLIP15.1 CLIP15.2 CLIP15.3 CLIP15.4 CLIP15.5 CN3.11 CN5.2 CN5.PAD1 CN5.PAD2 CN5.PAD3 CN5.PAD4 D13.A D18.A M1.1 M2.1 M3.1 M5.1 M6.1 M7.1 M10.1 R93.1(TP-1) R96.1(TP-1) R219.2 R234.2(TP-2) SF1.1 SF2.1 SF4.1 SF6.1 SF7.1 U25.5 U27.5 U27.PAD1
VDD12V_POE: C313.1 D16.A L12.2 R217.1(TP-1)
VDD13_12: C323.1(TP-1) FB12.1 FB14.2
VDD_PSE_M1: CN3.18 D15.3
VDD_PSE_M2: CN3.16 D14.3
VDD_PSE_P1: CN3.17 D15.4
VDD_PSE_P2: CN3.15 D14.4
AUX_5V_EN: R239.1(TP-1)
G_LED_FB1: LED26.2
G_LED_FB2: LED23.2
G_LED_FB3: LED47.2
G_LED_FB4: LED39.2
G_LED_FB5: LED10.2
G_LED_FB6: LED2.2
GLH: C325.2(TP-2) CN3.PAD1 CN3.PAD2
LED_G_POWER: LED1.1 LED9.1 LED24.1 LED25.1 LED40.1 LED48.1
LED_R_POWER: LED1.3 LED9.3 LED24.3 LED25.3 LED40.3 LED48.3
POE_ADP: R56.2(TP-2) U4.12
POE_CTL: R10.2(TP-2) R17.2(TP-2) U4.1 U22.4
POE_PRI_SW_NODE: D9.A Q1.5 Q1.6 Q1.7 Q1.8 T1.4
POE_RTN: C27.2 C49.1 C52.2 C248.2 C249.2 C258.2 C259.2 C275.2(TP-2) C278.2 R20.2 R48.2 R49.2(TP-2) R56.1(TP-1) T1.2 U4.6 U22.3
POE_VB: C27.1 C28.1(TP-1) R17.1(TP-1) U4.2
POE_VDD: C52.1 C258.1 C273.1 D11.C FB9.2 L10.1 R54.1 U4.8 U4.9
POE_VDD_CN: D14.1 D15.1 FB9.1
POE_VSS: C273.2 D11.A FB10.2 R55.1 U4.7
POE_VSS_CN: D14.2 D15.2 FB10.1
R_LED_IFB1: LED26.4
R_LED_IFB2: LED23.4
R_LED_IFB3: LED47.4
R_LED_IFB4: LED39.4
R_LED_IFB5: LED10.4
R_LED_IFB6: LED2.4
RGMII_LED_10_100: R99.2(TP-2)
RGMII_LED_1000: R96.2(TP-2) R98.2(TP-2)
RGMII_LED_ACT: R93.2(TP-2) R97.2(TP-2)
RGMII_TRXN0: CN3.2
RGMII_TRXN1: CN3.4
RGMII_TRXN2: CN3.8
RGMII_TRXN3: CN3.10
RGMII_TRXP0: CN3.1
RGMII_TRXP1: CN3.3
RGMII_TRXP2: CN3.7
RGMII_TRXP3: CN3.9
SYS_5V: C284.1(TP-1) C327.1 C328.1 C329.1 C331.1 L14.2 R223.1(TP-1) R301.1(TP-1)
VGEN5_2V8: R237.1(TP-1)
N3015967: C311.1(TP-1) U27.7
N3025436: C284.2(TP-2) R223.2(TP-2) R234.1(TP-1) U27.2
N3057658: C286.2(TP-2) R237.2(TP-2) R238.2(TP-2) R239.2(TP-2) U27.1
N3078807: R235.2(TP-2) U27.4
N3079141: C285.1(TP-1) R235.1(TP-1) U27.3
N17701582: LED25.2 LED27.1
N17701584: LED25.4 LED27.3
N17701586: LED27.2 LED29.1
N17701588: LED27.4 LED29.3
N17701590: LED29.2 LED31.1
N17701592: LED29.4 LED31.3
N17701594: LED33.2 LED35.1
N17701596: LED33.4 LED35.3
N17701598: LED31.2 LED33.1
N17701600: LED31.4 LED33.3
N17701602: LED35.2 LED37.1
N17701604: LED35.4 LED37.3
N17701700: LED36.1 LED38.2
N17701702: LED36.3 LED38.4
N17701704: LED21.2 LED23.1
N17701706: LED21.4 LED23.3
N17702195: LED37.4 LED39.3
N17702197: LED37.2 LED39.1
N17702222: LED34.1 LED36.2
N17702224: LED34.3 LED36.4
N17702236: LED32.1 LED34.2
N17702240: LED32.3 LED34.4
N17702242: LED30.1 LED32.2
N17702244: LED30.3 LED32.4
N17702269: LED26.1 LED28.2
N17702271: LED26.3 LED28.4
N17702317: LED28.1 LED30.2
N17702327: LED28.3 LED30.4
N17702414: LED40.2 LED41.1
N17702416: LED40.4 LED41.3
N17702418: LED41.2 LED42.1
N17702420: LED41.4 LED42.3
N17702422: LED42.2 LED43.1
N17702424: LED42.4 LED43.3
N17702426: LED44.2 LED45.1
N17702428: LED44.4 LED45.3
N17702430: LED43.2 LED44.1
N17702432: LED43.4 LED44.3
N17702434: LED45.2 LED46.1
N17702436: LED45.4 LED46.3
N17702438: LED46.2 LED47.1
N17702440: LED46.4 LED47.3
N17702495: LED1.2 LED11.1
N17702497: LED1.4 LED11.3
N17702499: LED11.2 LED13.1
N17702501: LED11.4 LED13.3
N17702503: LED13.2 LED15.1
N17702505: LED13.4 LED15.3
N17702507: LED17.2 LED19.1
N17702509: LED17.4 LED19.3
N17702511: LED15.2 LED17.1
N17702513: LED15.4 LED17.3
N17702515: LED19.2 LED21.1
N17702517: LED19.4 LED21.3
N17702581: LED38.1 LED48.2
N17702583: LED38.3 LED48.4
N17736265: LED22.1 LED24.2
N17736966: LED22.3 LED24.4
N17737669: LED20.1 LED22.2
N17738374: LED20.3 LED22.4
N17739081: LED18.1 LED20.2
N17739790: LED18.3 LED20.4
N17740501: LED16.1 LED18.2
N17741214: LED16.3 LED18.4
N17741929: LED14.1 LED16.2
N17742646: LED14.3 LED16.4
N17743365: LED12.1 LED14.2
N17744086: LED12.3 LED14.4
N17744809: LED10.1 LED12.2
N17745534: LED10.3 LED12.4
N17756919: LED8.1 LED9.2
N17756921: LED8.3 LED9.4
N17756923: LED7.1 LED8.2
N17756925: LED7.3 LED8.4
N17756927: LED6.1 LED7.2
N17756929: LED6.3 LED7.4
N17756931: LED5.1 LED6.2
N17756933: LED5.3 LED6.4
N17756935: LED4.1 LED5.2
N17756937: LED4.3 LED5.4
N17756939: LED3.1 LED4.2
N17756941: LED3.3 LED4.4
N17756943: LED2.1 LED3.2
N17756945: LED2.3 LED3.4
N25585706: C264.2(TP-2) C276.2(TP-2) R216.2 R219.1 U25.4
N25585768: R193.2(TP-2) T1.1
N25585770: C276.1(TP-1) D12.P R208.1(TP-1) U22.2 U25.3
N25585804: C275.1(TP-1) C278.1 D10.3 U4.4
N25585918: C250.2(TP-2) D9.C R172.2(TP-2)
N25586657: C233.2 C248.1 C249.1 C250.1(TP-1) L10.2 R172.1(TP-1) T1.3
N25586716: D12.N R213.1(TP-1) R216.1 R217.2(TP-2) R236.1(TP-1)
N25586736: C259.1 D10.1 R193.1(TP-1)
N25586772: R48.1 U4.13
N25586778: R49.1(TP-1) U4.14
N25586811: R213.2(TP-2) U22.1
N25586821: R11.2(TP-2) U4.3
N25586882: C288.1 C291.1 L12.1 T1.9 T1.10
N25586908: Q1.4 R16.2(TP-2)
N25586910: Q1.1 Q1.2 Q1.3 R11.1(TP-1) R20.1
N25587015: D13.C R243.1 T1.7 T1.8
N25587094: R54.2 U4.10
N25587194: C264.1(TP-1) R208.2(TP-2)
N25587240: C283.1 D12.NP R236.2(TP-2)
N25587378: R55.2 U4.11
N25587545: R16.1(TP-1) U4.5
N25594365: C153.2(TP-2) CN3.5 CN3.6
N25594481: CN3.12 R97.1(TP-1)
N25594574: CN3.13 R98.1(TP-1)
N25594579: CN3.14 R99.1(TP-1)
N25600625: C322.1(TP-1) CN5.1 D18.C FB13.1
N25600639: D17.A1 D17.A2 FS1.2
N25600655: C309.1 C320.1 D16.C D17.C FB14.1
N25600703: C318.1(TP-1) FB13.2 FS1.1
N25856521: C292.1(TP-1) R243.2
N26013479: C28.2(TP-2) R10.1(TP-1)

Pads without a net: D10 2; NOREF#3 1; NOREF#5 1; NOREF#8 1; NOREF#9 1; NOREF#10 1; NOREF#11 1; NOREF#12 1; NOREF#13 1; T1 5 6; U25 1 2

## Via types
v1: diameter 0.508, hole 0.254, TOP to BOTTOM, 837 vias

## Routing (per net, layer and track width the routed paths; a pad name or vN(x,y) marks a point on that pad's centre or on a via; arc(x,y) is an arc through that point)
5VDDM:
  vias: v1(34.15,86.85) v1(34.17,88.15) v1(34.53,87.49) v1(34.93,88.15) v1(34.86,86.9) v1(35.31,87.51) v1(35.69,88.15) v1(35.72,86.9) v1(36.08,87.51) v1(36.44,86.91) v1(36.46,88.15) v1(36.81,87.49)
5VDDM_VIN: length 15.8
  BOTTOM w0.508: 26.78,115.3 24.62,115.3 23.86,116.06 23.86,124.19 25.28,125.61 R238.1
GND: length 24.7
  TOP w0.381: R93.1 v1(90.79,121.52) ; v1(90.83,120.37) 90.83,120.37 R96.1
  TOP w0.508: M5.1 21.02,101.4 ; M5.1 17.6,106.73 ; M5.1 21.01,104.82 ; C153.1 91.91,117.59 v1(91.68,117.81)
  BOTTOM w0.508: C283.2 v1(48.02,129.24) ; 36.81,184.11 36.81,184.9 ; 35.63,175.97 34.27,175.97 ; R219.2 v1(50.51,126.22) ; C286.1 v1(31,126.81) ; U25.5 v1(42.95,129.29) ; 35.29,184.11 35.29,184.9 ; 35.54,173.91 35.52,173.91 35.29,174.14 35.29,174.83 ; v1(35.29,128.51) 35.29,128.31 35.29,128.31 C285.2 ; R234.2 v1(34.17,128.51)
  vias: v1(10.78,180.22) v1(10.78,178.5) v1(10.78,176.74) v1(10.79,171.26) v1(10.77,169.78) v1(10.8,168.44) v1(10.83,166.81) v1(10.83,165.06) v1(10.83,163.26) v1(10.83,161.5) v1(10.8,159.67) v1(10.83,155.15) v1(10.78,139.3) v1(10.78,137.65) v1(10.78,136.25) v1(10.78,134.6) v1(10.78,132.95) v1(10.78,131.17) v1(10.78,129.4) v1(10.78,127.75) v1(10.78,123.1) v1(10.77,121.56) v1(10.79,120.23) v1(10.78,118.62) v1(10.78,116.86) v1(10.78,115.06) v1(10.78,113.31) v1(10.81,111.53) v1(10.78,107.3) v1(10.78,105.77) v1(10.8,104.43) v1(10.8,102.8) v1(10.8,101.05) v1(10.8,99.25) v1(10.8,97.49) v1(10.82,95.77) v1(10.8,91.07) v1(10.78,89.52) v1(10.78,88.12) v1(10.78,86.6) v1(10.78,84.82) v1(10.78,83.04) v1(10.78,81.26) v1(10.78,79.49) v1(10.83,37.53) v1(10.83,35.77) v1(10.77,27.36) v1(10.76,25.81) v1(10.77,24.29) v1(10.77,22.7) v1(10.78,21.39) v1(10.85,153.63) v1(10.88,152.28) v1(10.88,150.66) v1(10.88,148.9) v1(10.88,147.1) v1(10.88,145.35) v1(10.85,143.52) v1(10.85,33.99) v1(10.85,32.19) v1(11.76,17.2) v1(12.3,186.6) v1(12.31,16.13) v1(13,15.1) v1(13.17,187.89) v1(13.91,14.05) v1(14.22,189.04) v1(15.01,13.08) v1(15.4,190) v1(15.86,24.15) v1(15.86,21.18) v1(15.93,18.26) v1(16.06,12.35) v1(16.54,190.71) v1(17.18,11.76) v1(21.3,192.02) v1(21.8,10.77) v1(22.64,192.03) v1(23.54,10.77) v1(24.23,192.02) v1(24.83,85.57) v1(24.88,162.67) v1(24.88,119.11) v1(24.88,118.22) v1(24.88,117.2) v1(24.88,116.19) v1(24.88,97.65) v1(24.88,92.69) v1(24.88,88.5) v1(24.94,80.82) v1(25,155.81) v1(25,148.19) v1(25,140.57) v1(25,132.95) v1(25.27,10.77) v1(25.78,192.03) v1(27.06,10.77) v1(27.16,123.05) v1(27.16,95.36) v1(27.16,90.66) v1(27.22,85.57) v1(27.35,192.03) v1(27.33,80.82) v1(27.8,109.84) v1(27.8,106.54) v1(27.92,123.05) v1(28.18,99.55) v1(28.81,87.49) v1(29.07,123.05) v1(29.83,123.05) v1(30.97,123.05) v1(30.97,95.87) v1(31.71,191.98) v1(31.73,123.05) v1(31.86,90.28) v1(31.99,10.78) v1(32.75,122.54) v1(32.75,121.78) v1(32.75,120.89) v1(33.17,14.85) v1(33.49,192.01) v1(33.58,122.67) v1(33.63,121.03) v1(33.79,10.78) v1(34.77,122.64) v1(34.77,121.05) v1(35.24,192.01) v1(35.57,10.78) v1(35.99,122.65) v1(35.95,121.05) v1(36.47,14.87) v1(37.04,192.01) v1(37.32,10.78) v1(37.52,122.51) v1(37.52,121.64) v1(37.52,120.69) v1(37.49,119.71) v1(37.83,130.54) v1(38.79,192.01) v1(38.83,14.87) v1(39.1,121.78) v1(39.1,117.97) v1(39.1,114.16) v1(39.13,10.78) v1(39.36,81.24) v1(39.61,99.93) v1(39.61,99.17) v1(39.61,98.15) v1(39.61,97.27) v1(39.61,96.12) v1(39.61,95.36) v1(39.61,94.34) v1(39.61,93.58) v1(39.99,90.53) v1(40.42,192.01) v1(40.88,10.78) v1(41.05,86.62) v1(41.22,14.87) v1(41.64,134.35) v1(41.75,81.24) v1(41.77,192.03) v1(41.77,109.58) v1(41.77,107.55) v1(42.02,114.03) v1(42.15,119.24) v1(42.4,109.58) v1(42.4,107.55) v1(42.5,10.78) v1(42.66,126.6) v1(42.78,119.24) v1(42.78,114.03) v1(43.29,192.03) v1(43.42,119.24) v1(43.43,86.62) v1(43.54,114.03) v1(43.81,14.87) v1(44.05,119.24) v1(44.31,114.03) v1(44.34,81.24) v1(45.2,99.81) v1(46.02,86.62) v1(47.15,81.24) v1(47.61,192.03) v1(47.99,10.78) v1(48.84,86.62) v1(49.36,192.03) v1(49.51,137.78) v1(49.64,105.14) v1(49.72,124.2) v1(49.79,10.78) v1(49.89,137.14) v1(50.4,137.78) v1(50.48,124.2) v1(50.78,137.14) v1(51.14,191.98) v1(51.13,125.37) v1(51.13,124.6) v1(51.29,137.78) v1(51.25,86.62) v1(51.42,95.49) v1(51.42,92.82) v1(51.57,10.8) v1(51.67,137.14) v1(52.82,126.48) v1(52.94,191.98) v1(53.32,106.66) v1(53.32,10.8) v1(53.45,126.48) v1(53.58,107.3) v1(53.61,86.62) v1(54.09,106.66) v1(54.34,107.3) v1(54.7,191.98) v1(54.85,106.66) v1(55.1,107.3) v1(55.13,10.8) v1(55.48,95.61) v1(55.48,92.95) v1(56.32,191.98) v1(56.88,10.8) v1(57.67,192.01) v1(58.51,10.8) v1(58.98,86.81) v1(59.19,192.01) v1(61.34,86.81) v1(61.96,95.49) v1(61.96,92.95) v1(62.72,106.54) v1(63.36,106.54) v1(63.62,192.03) v1(63.74,107.93) v1(63.74,107.3) v1(63.73,86.81) v1(64.02,10.78) v1(65.37,192.03) v1(65.82,10.78) v1(66.02,112.76) v1(66.02,112.12) v1(66.02,95.61) v1(66.02,92.95) v1(66.32,86.81) v1(67.15,191.98) v1(67.6,10.8) v1(68.06,116.95) v1(68.06,116.32) v1(68.06,115.68) v1(68.06,109.71) v1(68.06,105.14) v1(68.69,116.95) v1(68.69,116.32) v1(68.69,115.68) v1(68.95,191.98) v1(69.13,86.81) v1(69.35,10.8) v1(69.45,126.86) v1(69.45,122.28) v1(70.09,126.86) v1(70.09,122.28) v1(70.71,191.98) v1(70.72,126.86) v1(70.72,122.28) v1(71.15,10.8) v1(71.51,92.73) v1(71.54,86.81) v1(72.33,191.98) v1(72.88,161.4) v1(72.91,10.8) v1(73.68,192.01) v1(73.77,161.4) v1(73.91,86.81) v1(74.23,95.63) v1(74.35,92.69) v1(74.53,10.8) v1(74.67,161.41) v1(75.2,192.01) v1(75.55,161.4) v1(76.31,161.4) v1(76.65,95.63) v1(76.76,92.69) v1(77.21,86.83) v1(79.01,95.63) v1(79.12,92.69) v1(79.43,10.78) v1(79.64,192.03) v1(79.57,86.83) v1(81.24,10.78) v1(81.39,192.03) v1(81.58,95.64) v1(81.63,92.71) v1(83.02,10.8) v1(83.17,191.98) v1(83.95,95.64) v1(83.99,92.71) v1(84.82,185.15) v1(84.82,180.07) v1(84.77,10.8) v1(84.97,191.98) v1(86.33,95.64) v1(86.38,92.71) v1(86.57,10.8) v1(86.72,191.98) v1(88.32,10.8) v1(88.35,191.98) v1(88.92,95.64) v1(88.97,92.71) v1(89.7,192.01) v1(89.95,10.8) v1(91.22,192.01) v1(91.42,94.6) v1(91.45,10.8) v1(93.58,98.03) v1(93.7,104.06) v1(93.7,103.37) v1(93.69,102.7) v1(95.67,192.03) v1(96.22,10.76) v1(97.42,192.03) v1(98.02,10.76) v1(99.2,191.98) v1(99.82,10.76) v1(100.08,184.92) v1(101,191.98) v1(101.57,10.76) v1(102.75,191.98) v1(103.38,10.76) v1(104.38,191.98) v1(105.13,10.76) v1(105.72,192.01) v1(106.76,10.76) v1(107.25,192.01) v1(111.36,10.78) v1(111.67,192.03) v1(113.17,10.78) v1(113.42,192.03) v1(114.97,10.78) v1(115.2,191.98) v1(116.72,10.78) v1(117,191.98) v1(118.53,10.78) v1(118.75,191.98) v1(120.28,10.78) v1(120.38,191.98) v1(121.73,192.01) v1(121.9,10.78) v1(123.25,192.01) v1(123.35,10.78) v1(127.49,10.78) v1(127.77,192.03) v1(129.3,10.78) v1(129.52,192.03) v1(131.1,10.78) v1(131.3,191.98) v1(132.85,10.78) v1(133.11,191.98) v1(134.65,10.78) v1(134.86,191.98) v1(136.41,10.78) v1(136.48,191.98) v1(137.83,192.01) v1(138.03,10.78) v1(139.35,192.01) v1(139.48,10.78) v1(143.49,10.78) v1(143.67,192.03) v1(145.3,10.78) v1(145.42,192.03) v1(147.1,10.78) v1(147.2,191.98) v1(148.85,10.78) v1(149.01,191.98) v1(150.66,10.78) v1(150.76,191.98) v1(152.38,191.98) v1(152.41,10.78) v1(153.73,192.01) v1(154.03,10.78) v1(155.25,192.01) v1(155.48,10.78) v1(159.57,192.03) v1(159.92,10.79) v1(161.32,192.03) v1(161.72,10.79) v1(163.1,191.98) v1(163.52,10.79) v1(164.91,191.98) v1(165.28,10.79) v1(166.66,191.98) v1(167.08,10.79) v1(168.28,191.98) v1(168.83,10.79) v1(169.63,192.01) v1(170.46,10.79) v1(171.15,192.01) v1(175.78,10.77) v1(176.18,192.03) v1(176.63,188.31) v1(177.53,10.77) v1(177.99,192.03) v1(178.99,188.31) v1(179.33,10.77) v1(179.79,192.03) v1(181.09,10.77) v1(181.44,192.01) v1(181.38,188.31) v1(181.38,183.84) v1(183.74,183.84) v1(183.95,16.9) v1(183.97,188.31) v1(185.64,11.77) v1(185.71,190.99) v1(186.13,183.84) v1(186.94,12.48) v1(187,190.26) v1(187.13,41.95) v1(187.22,87.58) v1(187.22,80.75) v1(187.17,61.6) v1(187.22,55.15) v1(187.17,48.5) v1(187.17,35.58) v1(187.27,74.15) v1(187.27,68.3) v1(187.36,94.28) v1(188.18,189.39) v1(188.25,13.47) v1(188.72,183.84) v1(189.35,14.57) v1(189.5,188.07) v1(190.34,15.91) v1(190.36,186.88) v1(191.04,185.58) v1(191.06,17.22) v1(192.03,181.15) v1(192.02,179.22) v1(192.02,177.54) v1(192.02,175.74) v1(192.02,171.32) v1(192.02,169.68) v1(192.02,167.75) v1(192.03,165.94) v1(192.03,164.12) v1(192,162.57) v1(192,160.91) v1(192,159.5) v1(192.02,155.19) v1(192.02,153.62) v1(192.01,151.68) v1(192,149.88) v1(192.01,148.09) v1(192,146.49) v1(192,144.83) v1(192,143.42) v1(192.01,139.21) v1(192.01,137.65) v1(192,135.71) v1(191.99,133.91) v1(192,132.11) v1(191.99,130.52) v1(191.99,128.86) v1(191.99,127.45) v1(192.02,123.3) v1(191.98,121.5) v1(191.97,119.56) v1(191.96,117.76) v1(191.97,115.97) v1(191.96,114.37) v1(191.96,112.71) v1(191.98,111.37) v1(192.03,106.11) v1(192.02,104.17) v1(192.01,102.37) v1(192.02,100.57) v1(192.01,98.97) v1(192.01,97.32) v1(192.03,95.97) v1(192.03,91.22) v1(192.03,89.56) v1(192.03,87.64) v1(192.02,85.84) v1(192.03,84.04) v1(192.02,82.45) v1(192.02,80.79) v1(192.02,79.37) v1(192.02,75.3) v1(192.02,73.66) v1(192.02,71.72) v1(192.01,69.92) v1(192.02,68.12) v1(192.01,66.52) v1(192.01,64.87) v1(192.01,63.45) v1(192.03,59.36) v1(192.03,57.71) v1(192.03,55.77) v1(192.02,53.97) v1(192.03,52.18) v1(192.02,50.58) v1(192.02,48.92) v1(192.02,47.51) v1(192.03,43.08) v1(192.03,41.13) v1(192.02,39.34) v1(192.03,37.54) v1(192.02,35.94) v1(192.02,34.29) v1(192.02,32.87) v1(192.03,31.31) v1(192.02,27.37) v1(192.03,25.82) v1(192.03,24.24) v1(192.03,22.62) v1(192.02,21.12)
VDD12V_POE: length 25.4
  IN1 w0.508: v1(60.92,118.83) 59.8,117.71 51.04,117.71 48.75,120 48.75,127.24 50.53,129.02 v1(51.77,129.02)
  BOTTOM w0.508: R217.1 51.77,129.83 v1(51.77,129.02)
VDD13_12: length 6.5
  BOTTOM w0.508: 43.67,99.32 v1(43.67,105.77)
  vias: v1(27.03,111.62) v1(27.29,112.25) v1(27.67,111.62) v1(28.05,112.25) v1(28.3,111.62) v1(28.69,112.25) v1(43.54,107.04) v1(44.05,106.41) v1(44.31,107.04) v1(44.43,105.77) v1(44.81,106.41) v1(45.07,107.04) v1(45.2,105.77) v1(45.58,106.41) v1(45.83,107.04) v1(45.96,105.77) v1(46.34,106.41)
VDD_PSE_M1: length 44.5
  IN2 w0.813: CN3.18 77.32,103.36 75.93,104.76 74.41,104.76 74.02,104.38 71.99,104.38 71.1,105.27 71.1,110.22 72.75,111.87 72.75,117.46 75.04,119.74 84.69,119.74 v1(85.45,120.51)
  BOTTOM w0.813: D15.3 v1(85.45,120.51)
VDD_PSE_M2: length 25.1
  BOTTOM w0.813: CN3.16 72.5,103.36 71.23,104.63 71.23,109.46 72.75,110.98 72.75,117.97 73.77,118.98 77.18,118.98 77.69,119.49 D14.3
VDD_PSE_P1: length 43.7
  IN1 w0.813: v1(82.28,120.76) 75.8,120.76 72.25,117.2 72.25,111.11 71.23,110.09 71.23,105.52 72.37,104.38 74.02,104.38 74.41,104.76 75.93,104.76 78.85,101.84 86.83,101.84 CN3.17
  BOTTOM w0.813: v1(82.28,120.76) 82.53,120.51 D15.4
VDD_PSE_P2: length 23.1
  TOP w0.813: v1(73.64,120.51) 72.63,119.49 72.63,110.09 71.23,108.7 71.23,104.53 CN3.15
  BOTTOM w0.813: D14.4 v1(73.64,120.51)
AUX_5V_EN: length 144.6
  TOP w0.102: v1(28.69,126.35) 20.55,134.48 20.55,179.72 30.04,189.21 88.67,189.21 96.04,181.83 96.04,177.16
  BOTTOM w0.102: R239.1 v1(28.69,126.35)
DRAM_D27:
  vias: v1(142.63,126.32)
G_LED_FB1: length 0.9
  TOP w0.381: LED26.2 191.4,94.81 v1(191.3,94.91)
G_LED_FB2: length 106.7
  TOP w0.381: LED23.2 v1(12.09,108.69)
  IN1 w0.381: v1(34.53,188.69) 33.88,189.34 28.46,189.34 20.15,181.04 20.15,109.54 19.3,108.69 v1(12.09,108.69)
  BOTTOM w0.381: 35.29,181.31 35.29,182.64 34.76,182.64 34.53,182.86 v1(34.53,188.69)
G_LED_FB3: length 141.8
  TOP w0.381: LED47.2 158.14,12.2 v1(157.33,13.01)
  IN1 w0.381: 19.74,18.35 23.87,14.23 29.9,14.23 31.11,13.01 v1(157.33,13.01)
G_LED_FB4: length 14.8
  TOP w0.381: LED39.2 v1(30.12,12.2)
  IN1 w0.381: 18.47,17.83 23.34,12.96 29.37,12.96 v1(30.12,12.2)
G_LED_FB5: length 132.8
  TOP w0.381: LED10.2 172.67,190.7 v1(172.68,190.69)
  IN2 w0.381: v1(172.68,190.69) 172.68,190.58 171.34,189.24 42.05,189.24 v1(41.51,188.71)
G_LED_FB6: length 3.2
  TOP w0.381: LED2.2 v1(44.68,190.55)
  BOTTOM w0.381: v1(44.68,190.55) 43.02,188.9
GLH:
  vias: v1(90.78,104.08) v1(90.79,103.35) v1(90.8,102.66)
LED_G_POWER: length 484.3
  TOP w0.381: LED24.1 190.74,108.63 v1(190.42,108.31) ; v1(158.12,190.58) 158.12,191.4 LED9.1 ; LED40.1 44.68,11.69 47.27,14.28 v1(47.27,14.28) ; LED1.1 30.12,190.73 v1(30.12,190.73) ; LED25.1 11.5,94.25 v1(11.5,95.07) ; LED48.1 v1(172.69,12.25)
  IN1 w0.381: v1(158.12,190.58) 156.85,189.3 45.74,189.3 v1(45.07,189.98) 30.87,189.98 v1(30.12,190.73) ; v1(47.27,14.28) 47.27,14.28 157.76,14.28 159.87,12.18 172.62,12.18 v1(172.69,12.25) 173.37,12.92 183.28,12.92 189.73,19.37 189.73,95.75 191.37,97.39 191.37,107.85 190.91,108.31 v1(190.42,108.31)
  IN2 w0.381: v1(11.5,95.07) 11.5,105.65 13.35,107.5 20.73,107.5 22.9,109.67 22.9,164.38 32.37,173.85 32.37,180.58 30.12,182.83 v1(30.12,190.73)
  BOTTOM w0.508: 45.42,189.62 v1(45.07,189.98)
LED_R_POWER: length 455.9
  TOP w0.381: v1(12.16,93.45) 10.95,93.45 10.63,93.77 LED25.3 ; v1(30.91,191.3) 30.91,191.71 30.46,192.16 LED1.3 ; v1(172.03,12.83) 172.03,11.05 172.44,10.64 LED48.3 ; LED9.3 158.51,192.16 159.15,191.52 159.15,190.65 v1(159.13,190.63) ; v1(190.74,107.68) 191.65,107.68 192.18,108.21 LED24.3 ; v1(46.79,14.92) 43.93,12.06 43.93,11.08 44.37,10.64 LED40.3
  IN1 w0.381: 66.72,188.67 157.17,188.67 v1(159.13,190.63) ; v1(46.79,14.92) 46.79,14.92 158.03,14.92 160.11,12.83 v1(172.03,12.83) 172.75,13.56 183.02,13.56 189.09,19.63 189.09,96.01 190.74,97.65 v1(190.74,107.68)
  IN2 w0.381: v1(30.91,191.3) 30.91,183.18 33,181.09 33,173.34 23.53,163.87 23.53,109.41 20.99,106.87 13.61,106.87 12.16,105.41 v1(12.16,93.45)
POE_ADP: length 2.5
  TOP w0.305: R56.2 87.74,141.97 87.5,142.21 U4.12
POE_CTL: length 57.1
  TOP w0.254: U4.1 89.51,149.59 90.81,150.89 90.81,153.81 90.15,154.47 R17.2 90.15,155.91 R10.2 90.13,156.35 89.65,156.83 58.02,156.83 v1(56.5,155.3)
  BOTTOM w0.254: U22.4 48.6,147.41 v1(56.5,155.3)
POE_PRI_SW_NODE:
  vias: v1(54.47,150.86) v1(54.47,150.1) v1(54.47,149.34) v1(54.47,148.45) v1(55.36,150.86) v1(55.36,150.1) v1(55.36,149.34) v1(55.36,148.45)
POE_RTN: length 10.1
  TOP w0.381: v1(85.96,148.07) 85.55,148.48 U4.6 85.55,151.02 v1(85.33,151.24)
  TOP w0.508: R48.2 v1(88.88,139.56) ; C27.2 v1(87.23,155.56) ; R56.1 v1(87.74,138.67) ; R49.2 v1(89.9,139.56)
  BOTTOM w0.508: C259.2 v1(68.44,141.21)
  BOTTOM w0.813: U22.3 v1(47.33,145.88)
  vias: v1(49.13,145.4) v1(49.51,144.76) v1(50.02,145.4) v1(50.4,144.76) v1(50.91,145.4) v1(51.42,144.76) v1(62.59,146.41) v1(63.23,146.41) v1(64.12,154.03) v1(64.88,154.03) v1(65.64,154.03) v1(66.4,154.03) v1(68.18,151.49) v1(68.69,154.03) v1(69.45,154.03) v1(70.21,154.03) v1(70.47,151.49) v1(70.98,154.03) v1(72.88,133.71) v1(72.88,132.95) v1(73.14,142.35) v1(73.14,139.68) v1(73.64,133.71) v1(73.64,132.95) v1(73.9,142.35) v1(73.9,139.68) v1(74.66,142.35) v1(74.66,139.68) v1(75.55,143.37) v1(75.55,138.29) v1(76.31,143.37) v1(76.31,138.29)
POE_VB: length 7.6
  TOP w0.381: C27.1 C28.1 88.63,153.04 90.15,153.04 R17.1 90.15,152.32 89.46,151.62 88.78,151.62 88.15,150.99 U4.2
POE_VDD: length 2.6
  TOP w0.381: U4.9 85.55,142.58 85.07,142.1 v1(84.06,142.1)
  vias: v1(78.72,141.59) v1(78.72,140.83) v1(78.72,140.06) v1(78.72,139.3) v1(81.01,142.1) v1(81.01,139.68) v1(81.77,142.1) v1(81.77,139.68) v1(82.53,142.1) v1(82.53,139.68) v1(84.06,143.62) v1(84.06,142.86)
POE_VDD_CN:
  vias: v1(74.28,127.11) v1(74.28,126.22) v1(74.79,128) v1(75.55,128) v1(82.28,126.98) v1(82.28,126.22) v1(83.04,126.98) v1(83.04,126.22)
POE_VSS: length 0.9
  TOP w0.508: R55.1 v1(86.34,138.67)
  vias: v1(83.68,136) v1(83.68,135.11) v1(84.06,150.1) v1(84.06,149.46) v1(84.44,136) v1(84.44,135.11) v1(84.44,133.84) v1(84.44,133.21) v1(84.44,132.44) v1(84.44,131.81) v1(85.2,133.84) v1(85.84,133.84) v1(86.47,133.84)
R_LED_IFB1: length 2.8
  TOP w0.381: v1(190.66,95.87) 191.25,95.87 192.15,94.96 LED26.4
R_LED_IFB2: length 1.9
  TOP w0.381: LED23.4 10.63,108.34 10.94,108.04 v1(12.1,108.04)
R_LED_IFB3: length 143.4
  TOP w0.381: LED47.4 158.51,10.64 158.92,11.04 158.92,12.32 v1(157.59,13.65)
  IN1 w0.381: 20.38,18.62 24.13,14.86 30.16,14.86 31.37,13.65 v1(157.59,13.65)
R_LED_IFB4: length 16.3
  TOP w0.381: LED39.4 30.45,10.64 30.82,11.01 v1(30.82,12.18)
  IN1 w0.381: v1(30.82,12.18) 30.82,12.4 29.63,13.59 23.61,13.59 19.52,17.67 19.52,17.67 19.11,18.09
R_LED_IFB5: length 114.9
  TOP w0.381: v1(171.89,190.69) 171.89,190.76 171.89,190.76 171.89,191.85 172.19,192.16 LED10.4
  IN2 w0.381: v1(171.89,190.69) 171.08,189.88 v1(59.42,189.88)
R_LED_IFB6: length 20.3
  TOP w0.381: LED2.4 44.39,192.16 43.8,191.57 v1(43.8,190.99)
  BOTTOM w0.381: v1(43.8,190.99) 44.05,191.25 44.86,191.25 46.13,189.98 57.64,189.98 58.28,190.61 59.67,190.61 61,189.29
RGMII_LED_10_100: length 5.6
  TOP w0.381: v1(91.92,118.41) 92.2,118.69 R99.2
  IN2 w0.381: v1(91.92,118.41) 91.78,118.55 91.78,123.1
RGMII_LED_1000: length 3.2
  TOP w0.381: R98.2 90.6,119.24 91.11,119.74 91.98,119.74 92.26,120.02 R96.2 92.67,120.37
RGMII_LED_ACT: length 3.2
  TOP w0.381: R97.2 90.17,120.52 90.59,120.94 91.81,120.94 92.01,121.14 92.01,121.27 R93.2 92.58,121.52
RGMII_TRXN0: length 17.7
  IN2 w0.102: 89.74,108.9 87.92,108.9 86.64,107.62 78.01,107.62 76.84,108.79 76.84,110.1 76.45,110.49 CN3.2
RGMII_TRXN1: length 17.5
  IN2 w0.102: 89.42,109.61 87.46,109.61 86.19,108.33 83.37,108.33 83.27,108.44 83.27,108.77 82.99,109.05 82.54,109.05 82.26,108.77 82.26,108.44 82.15,108.33 81.95,108.33 81.85,108.44 81.85,108.97 81.57,109.25 81.11,109.25 80.83,108.98 80.83,108.44 80.73,108.33 79.62,108.33 79.24,108.71 79.24,110.44 78.48,111.21 78.48,111.95 CN3.4
RGMII_TRXN2: length 21.2
  IN2 w0.102: CN3.8 83.6,111.99 83.6,111.1 84.25,110.46 84.25,109.65 84.85,109.04 85.73,109.04 87.02,110.34 89.07,110.34 89.29,110.56 89.29,110.7 88.79,111.2 88.79,111.59 89.11,111.91 89.52,111.91 90.01,111.42 90.15,111.42 90.3,111.56 90.3,111.71 89.83,112.18 89.83,112.56 90.15,112.88 90.56,112.88 91.01,112.42 91.16,112.42 91.3,112.57 91.3,112.71 90.82,113.19 90.82,113.61 91.11,113.9 91.55,113.9 92.02,113.43 92.16,113.43 92.31,113.58 92.31,113.72 91.85,114.18 91.85,114.55 92.17,114.87 92.59,114.87 93.03,114.44
RGMII_TRXN3: length 23.1
  IN2 w0.102: 92.93,116.92 92.79,116.92 92.36,117.34 91.95,117.34 91.63,117.02 91.63,116.64 92.07,116.2 92.07,116.06 91.92,115.92 91.78,115.92 90.85,116.84 90.43,116.84 90.11,116.52 90.11,116.14 91.06,115.2 91.06,115.06 90.91,114.91 90.77,114.91 89.8,115.88 89.39,115.88 89.07,115.56 89.07,115.17 90.05,114.19 90.05,114.05 89.91,113.9 89.76,113.9 88.74,114.92 88.34,114.92 88.02,114.6 88.02,114.21 89.05,113.18 89.05,113.04 88.9,112.9 88.76,112.9 88.18,113.47 87.77,113.47 87.45,113.15 87.45,112.77 88.04,112.18 88.04,112.03 87.13,111.13 86.6,111.13 86.26,111.47 86.26,112.11 CN3.10
RGMII_TRXP0: length 17.3
  IN2 w0.102: 89.86,108.6 88.05,108.6 86.77,107.32 86.43,107.32 77.88,107.32 76.54,108.66 76.54,109.97 76.3,110.2 75.46,110.2 CN3.1
RGMII_TRXP1: length 17.6
  IN2 w0.102: 89.55,109.31 87.59,109.31 86.31,108.03 83.25,108.03 82.97,108.31 82.97,108.64 82.87,108.74 82.66,108.74 82.56,108.64 82.56,108.31 82.28,108.03 81.82,108.03 81.54,108.31 81.54,108.85 81.44,108.95 81.24,108.95 81.14,108.85 81.14,108.31 80.86,108.03 79.49,108.03 78.93,108.59 78.93,110.32 78.42,110.83 78.01,110.83 77.72,110.55 CN3.3
RGMII_TRXP2: length 20.9
  IN2 w0.102: CN3.7 82.8,110.48 83.01,110.68 83.6,110.68 83.94,110.34 83.94,109.52 84.72,108.74 85.86,108.74 87.15,110.03 89.2,110.03 89.59,110.43 89.59,110.83 89.09,111.33 89.09,111.46 89.23,111.6 89.39,111.6 89.88,111.11 90.28,111.11 90.6,111.44 90.6,111.83 90.13,112.3 90.13,112.44 90.27,112.58 90.43,112.58 90.89,112.12 91.28,112.12 91.61,112.44 91.61,112.84 91.13,113.32 91.13,113.49 91.24,113.6 91.42,113.6 91.89,113.13 92.29,113.13 92.61,113.45 92.61,113.85 92.15,114.31 92.15,114.42 92.3,114.57 92.47,114.57 92.9,114.13
RGMII_TRXP3: length 23.2
  IN2 w0.102: 93.05,116.62 92.66,116.62 92.24,117.04 92.08,117.04 91.93,116.9 91.93,116.77 92.37,116.33 92.37,115.94 92.05,115.61 91.65,115.61 90.73,116.54 90.56,116.54 90.42,116.39 90.42,116.27 91.36,115.32 91.36,114.93 91.04,114.61 90.64,114.61 89.68,115.57 89.52,115.57 89.38,115.43 89.38,115.3 90.36,114.32 90.36,113.92 90.03,113.6 89.64,113.6 88.62,114.62 88.47,114.62 88.33,114.48 88.33,114.33 89.35,113.31 89.35,112.91 89.03,112.59 88.63,112.59 88.06,113.17 87.9,113.17 87.75,113.02 87.75,112.89 88.34,112.3 88.34,111.91 87.26,110.82 86.24,110.82 CN3.9
SYS_5V: length 39.3
  TOP w0.254: v1(32.27,98.27) 23.99,106.55 23.99,122.54 26.78,125.33 31.67,125.33 v1(32.37,126.04)
  BOTTOM w0.254: v1(32.37,126.04) R223.1 C284.1
VGEN5_2V8: length 0.7
  BOTTOM w0.381: R237.1 v1(29.73,126.3)
N3015967: length 3
  BOTTOM w0.508: C311.1 33.56,117.23 34.17,117.84 U27.7
N3025436: length 4.4
  BOTTOM w0.254: U27.2 R234.1 33.68,126.86 33.58,126.75 R223.2 C284.2
N3057658: length 5.4
  BOTTOM w0.102: R238.2 R239.2 28.71,124.83 R237.2 30.13,124.83 30.46,124.49 C286.2 32.04,124.49 32.1,124.55 U27.1
N3078807: length 3.7
  BOTTOM w0.508: U27.4 36.71,125.44 37.05,125.78 37.05,127.18 36.59,127.64 R235.2
N3079141: length 3.4
  BOTTOM w0.508: R235.1 C285.1 35.29,125.71 35.44,125.55 U27.3
N17701582: length 16.1
  TOP w0.381: LED25.2 v1(12.15,92.68) ; LED27.1 v1(12.12,78.13)
  IN1 w0.381: v1(12.12,78.13) 12.18,78.19 12.18,92.65 v1(12.15,92.68)
N17701584: length 15.8
  TOP w0.381: LED27.3 10.63,78.43 11.13,78.93 v1(11.55,78.93) ; LED25.4 10.63,92.36 11.08,91.91 v1(11.53,91.91)
  IN1 w0.381: v1(11.55,78.93) 11.55,91.89 v1(11.53,91.91)
N17701586: length 0.9
  TOP w0.381: v1(12.2,76.66) 12.18,76.68 LED27.2
  IN1 w0.381: 12.29,76.57 v1(12.2,76.66)
N17701588: length 2.6
  TOP w0.381: 11.11,63 10.63,62.53 LED29.3 ; v1(11.6,75.86) 11.1,75.86 10.63,76.32 LED27.4
N17701592: length 2.2
  TOP w0.381: LED29.4 10.63,60.17 11.03,59.78 ; 11.2,47.07 10.63,46.51 LED31.3
N17701594: length 1.1
  TOP w0.381: LED35.1 v1(12,20.5)
  IN1 w0.381: v1(12,20.5) 12.2,20.7
N17701596: length 2.7
  TOP w0.381: v1(11.57,21.01) 10.72,20.16 LED35.3 ; LED33.4 10.63,28.34 11.1,27.87
N17701600: length 2.1
  TOP w0.381: 11.12,31.13 10.63,30.65 LED33.3 ; 11.06,43.95 10.63,44.38 LED31.4
N17701602: length 9.7
  TOP w0.381: LED37.1 18.51,12.6 v1(18.06,13.05) ; v1(12.78,18.33) 12.54,18.57 11.96,18.57
  IN1 w0.381: v1(12.78,18.33) v1(18.06,13.05)
N17701604: length 10.3
  TOP w0.381: LED37.3 17.8,11.7 v1(17.8,12.34) ; v1(12.38,17.77) 11.78,17.77 11.26,18.3
  IN1 w0.381: v1(12.38,17.77) 12.38,17.75 v1(17.8,12.34)
N17701700: length 9.9
  TOP w0.381: LED36.1 v1(189.78,18.53) ; LED38.2 v1(184.24,12.98)
  IN1 w0.381: v1(189.78,18.53) v1(184.24,12.98)
